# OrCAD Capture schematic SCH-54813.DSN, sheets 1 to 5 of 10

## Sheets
1 01 Title Page, Notes: title: PNEV7642A; rev: B1; company: NXP Semiconductors; note: SCH-54813 PDF: SPF-54813; note: 6501 William Cannon Drive West; note: Austin, TX 78735-8598
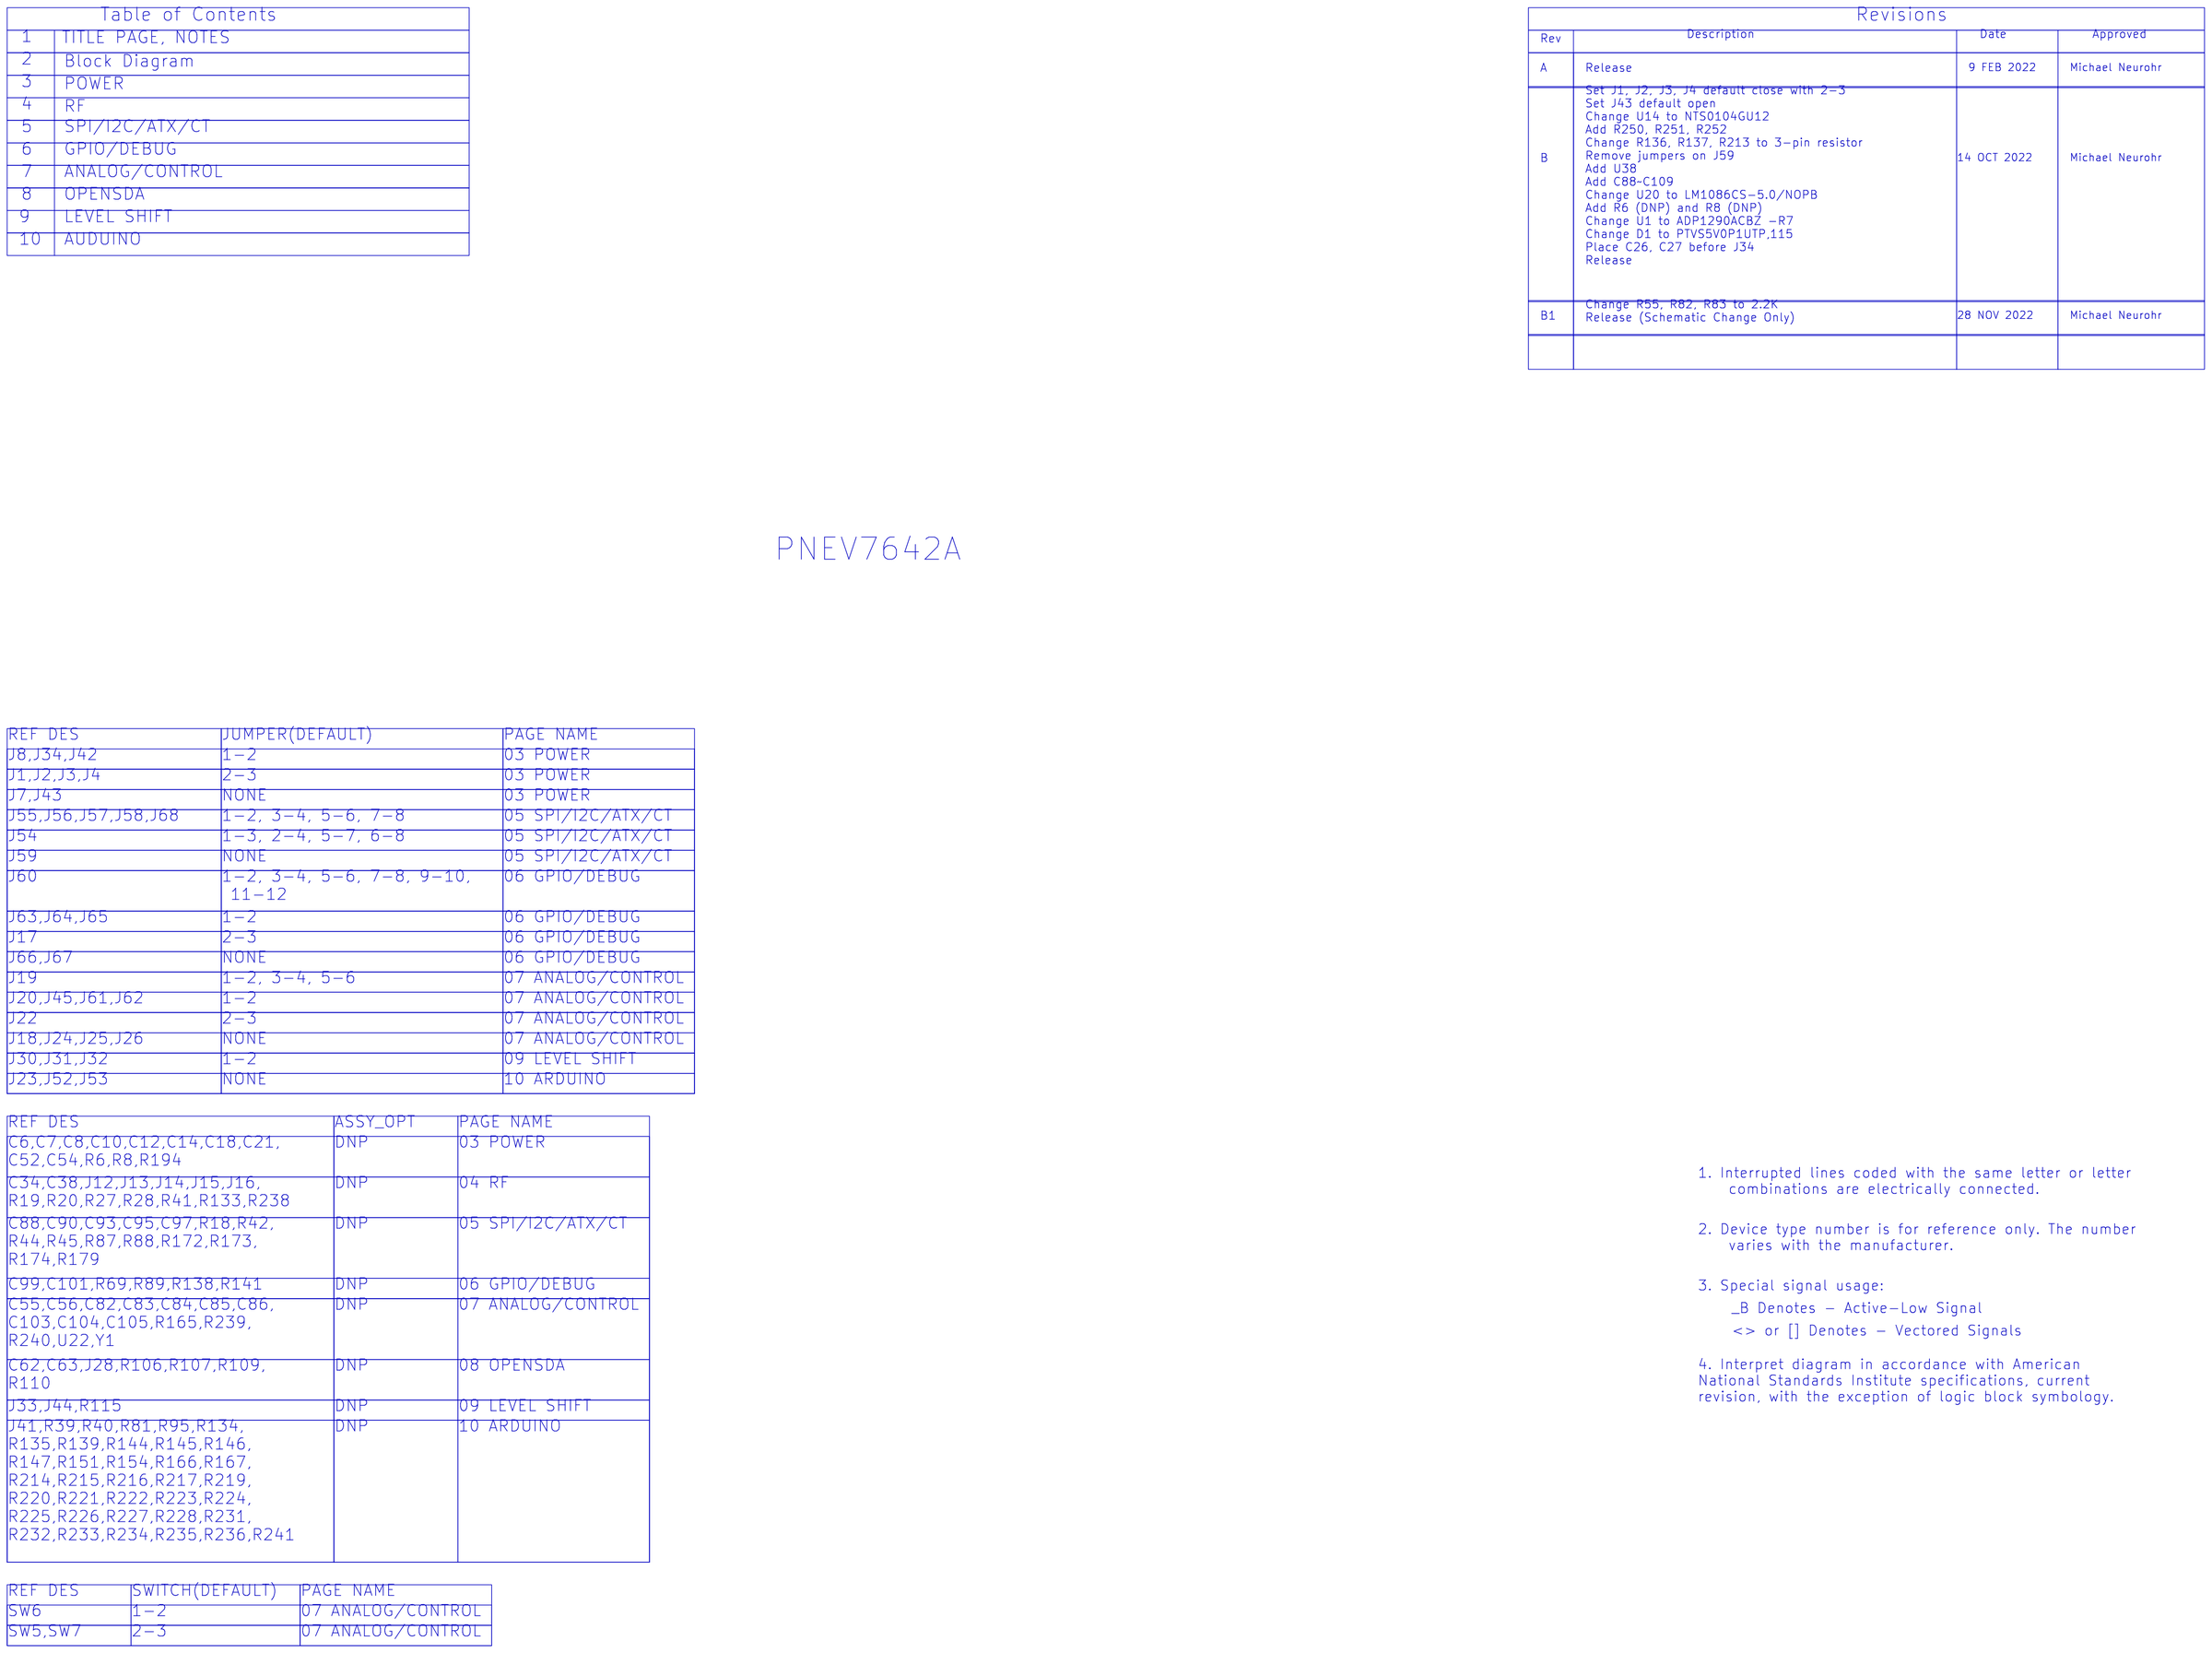
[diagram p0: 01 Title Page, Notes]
2 02 Block Diagram
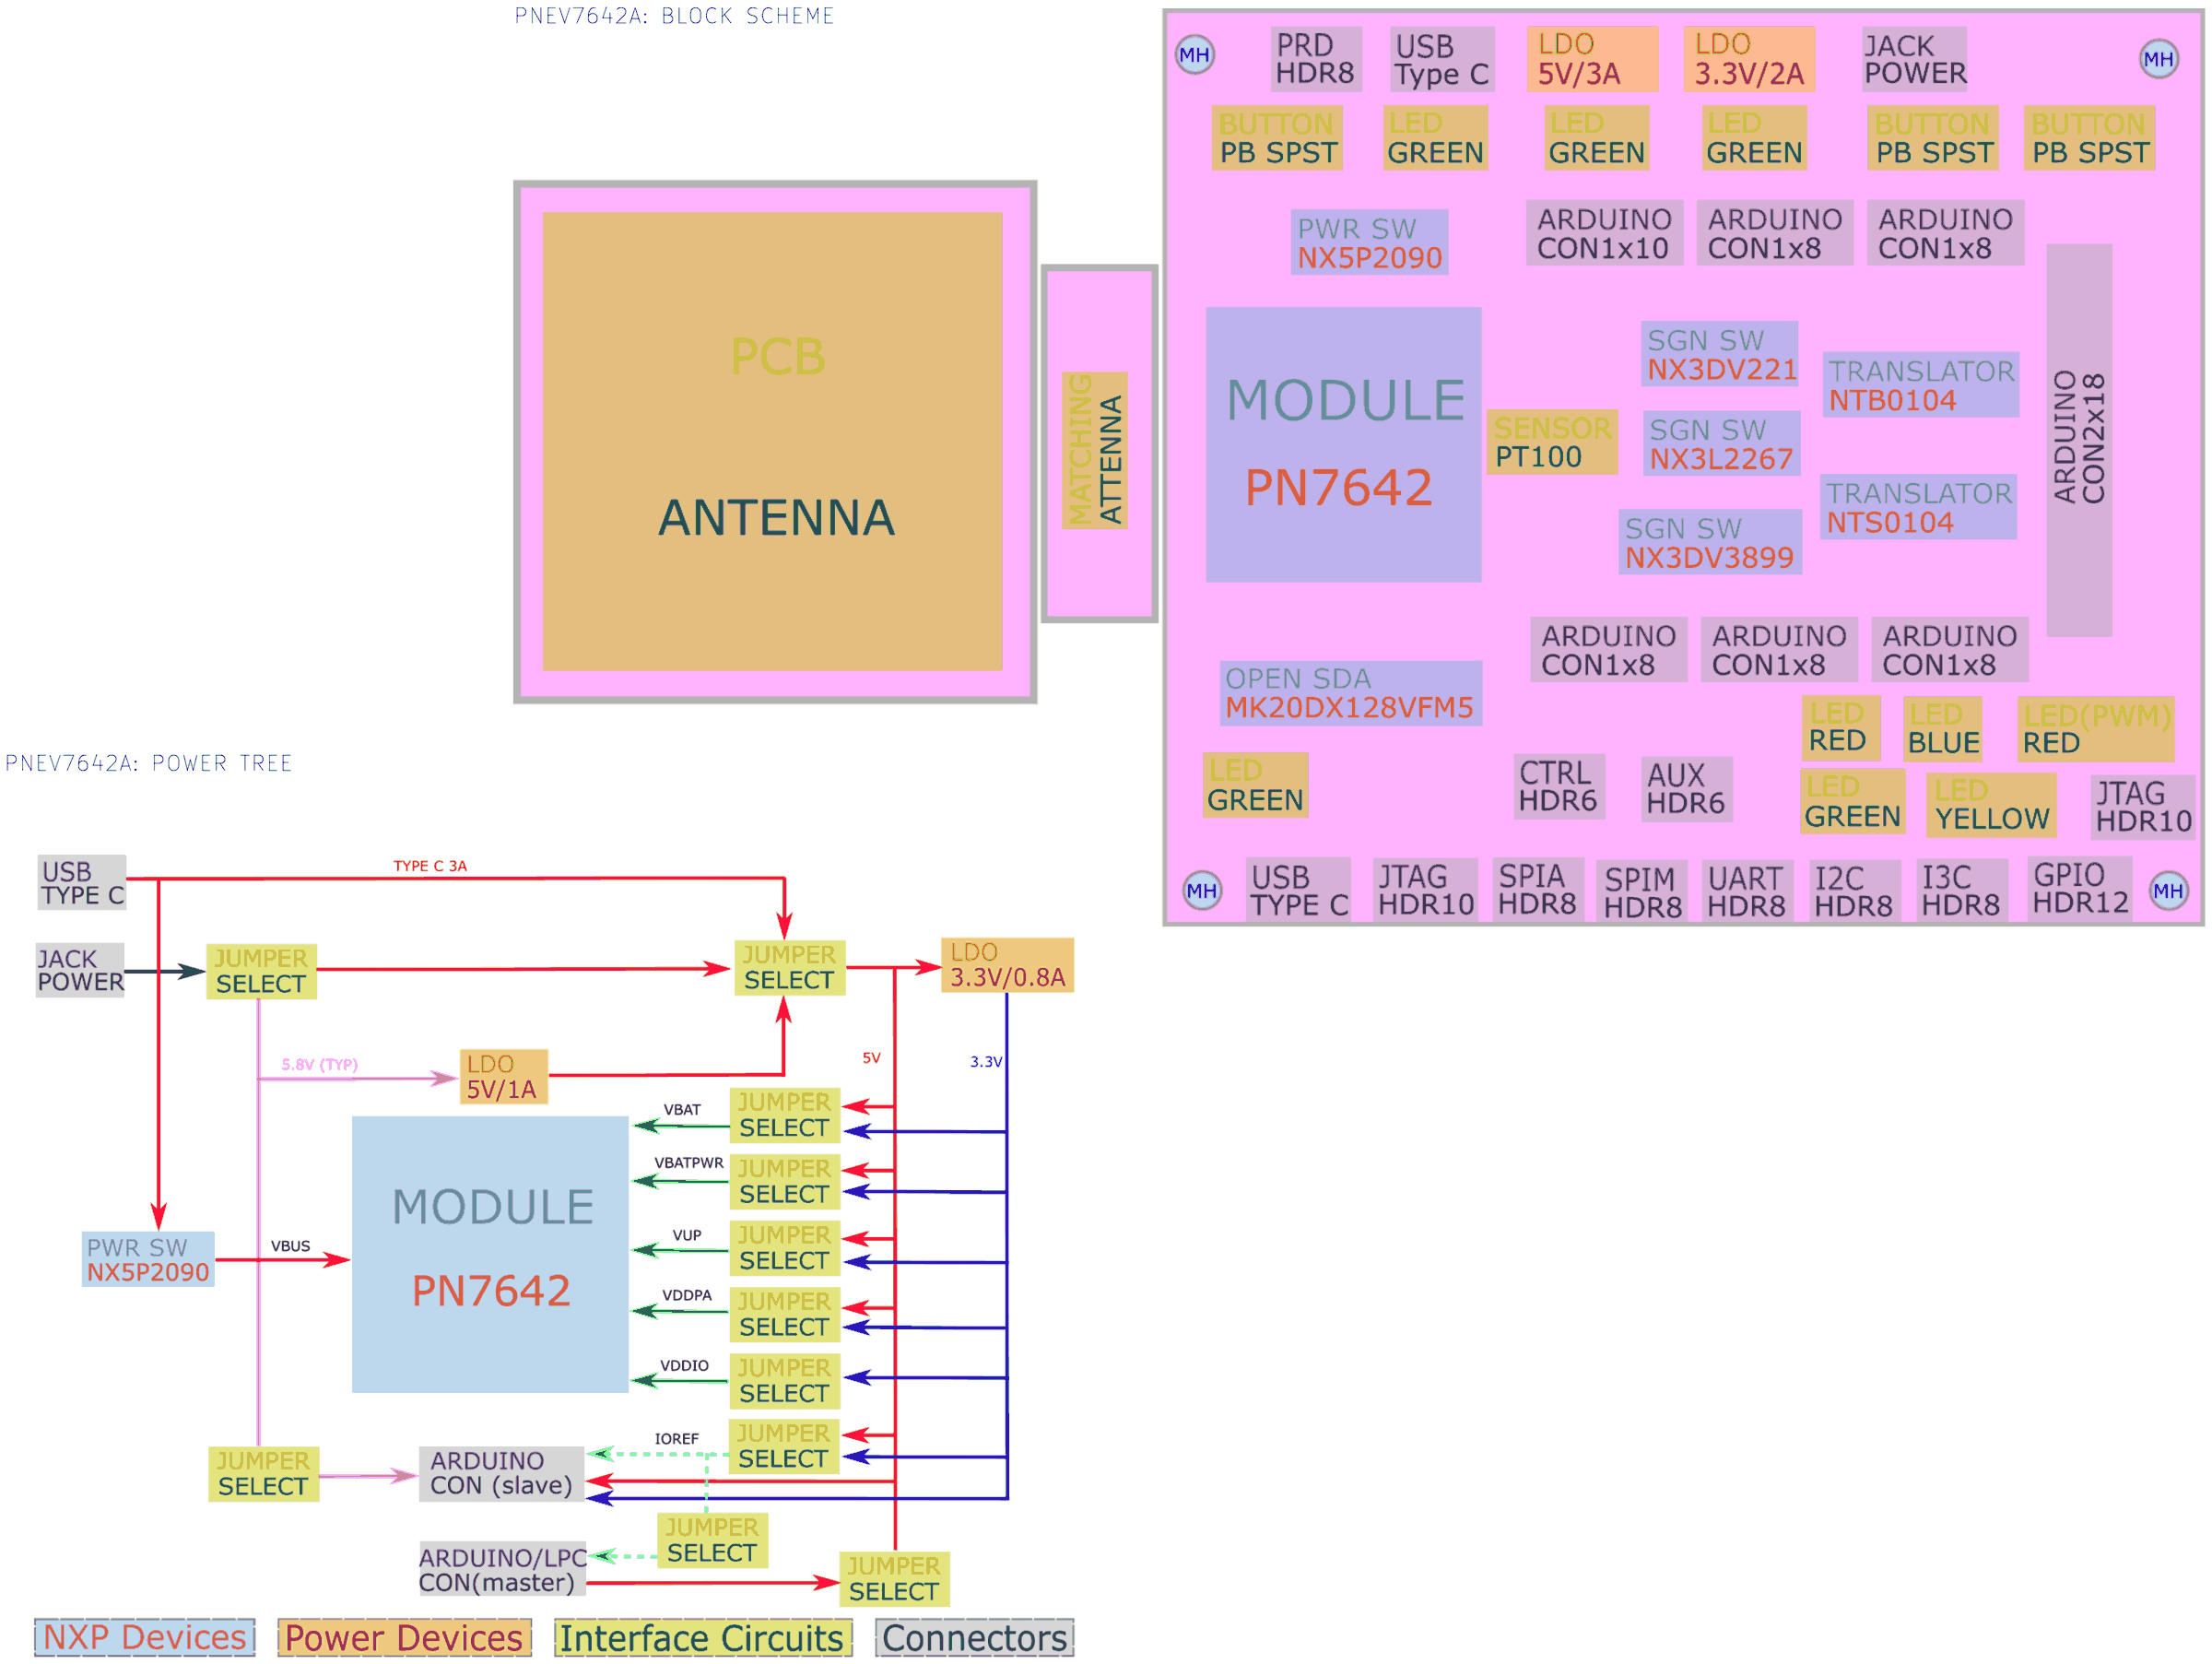
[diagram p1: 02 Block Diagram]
3 03 POWER: size C
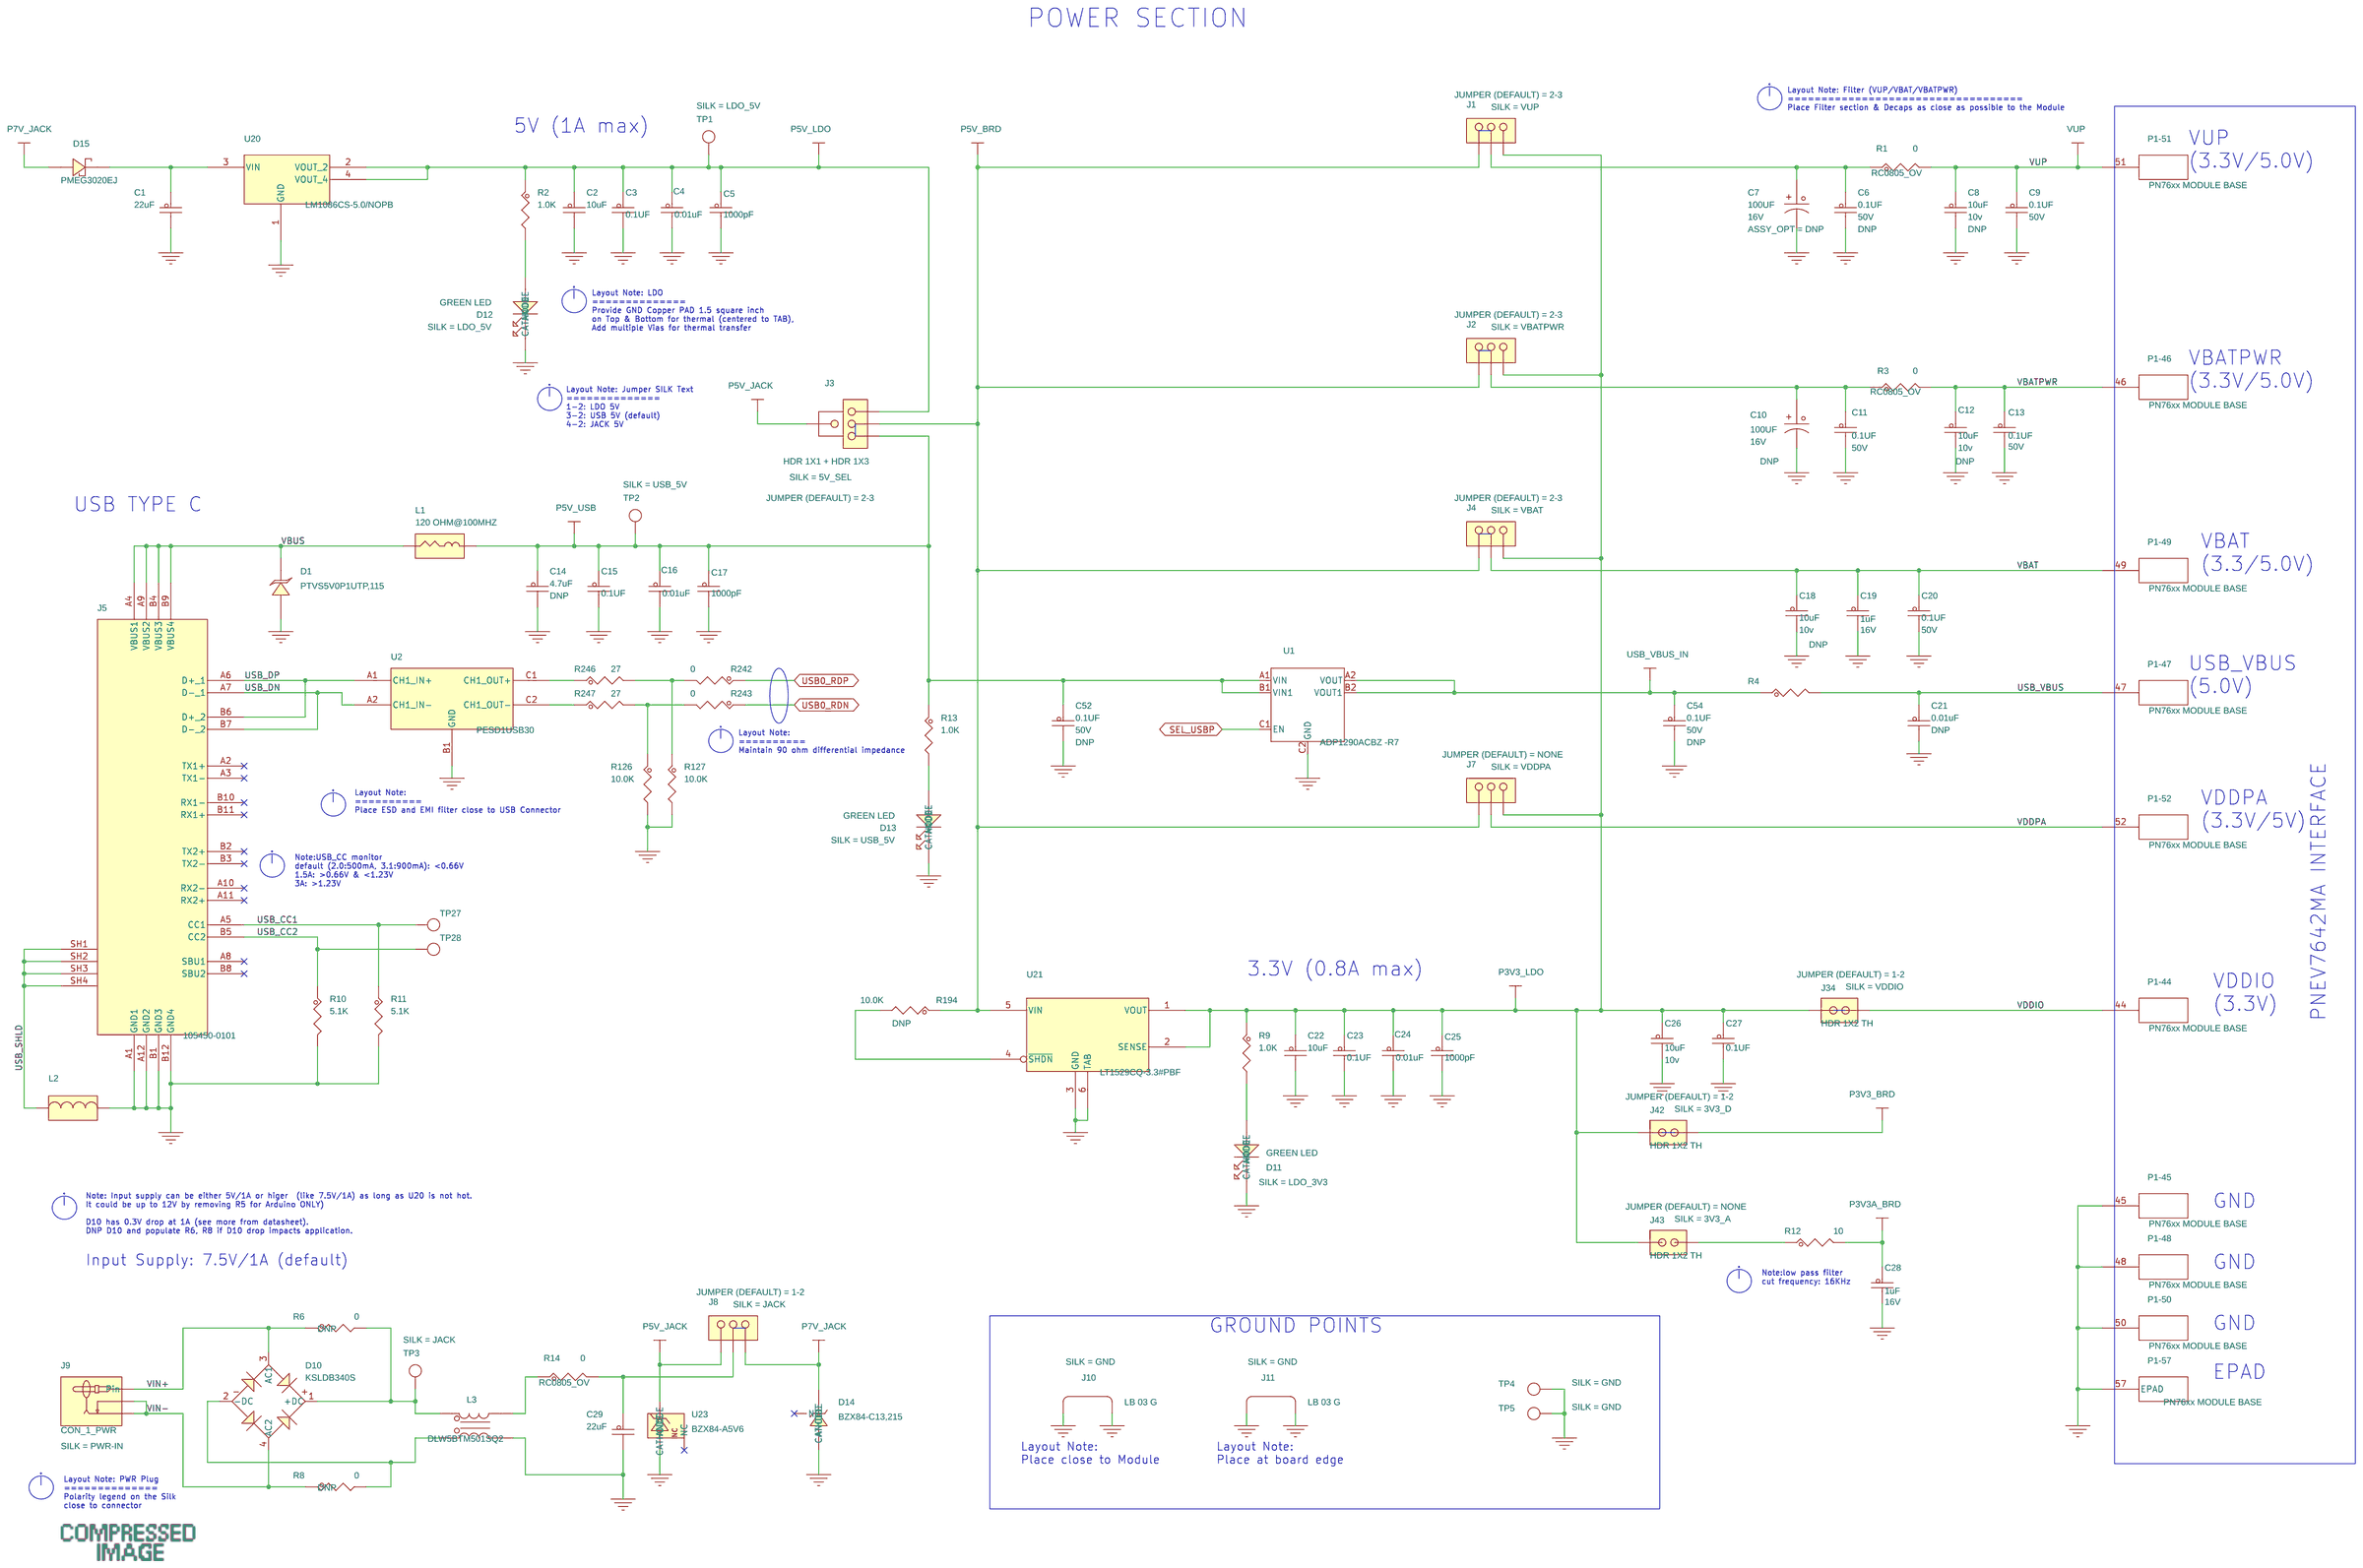
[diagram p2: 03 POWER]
4 04 RF: size C
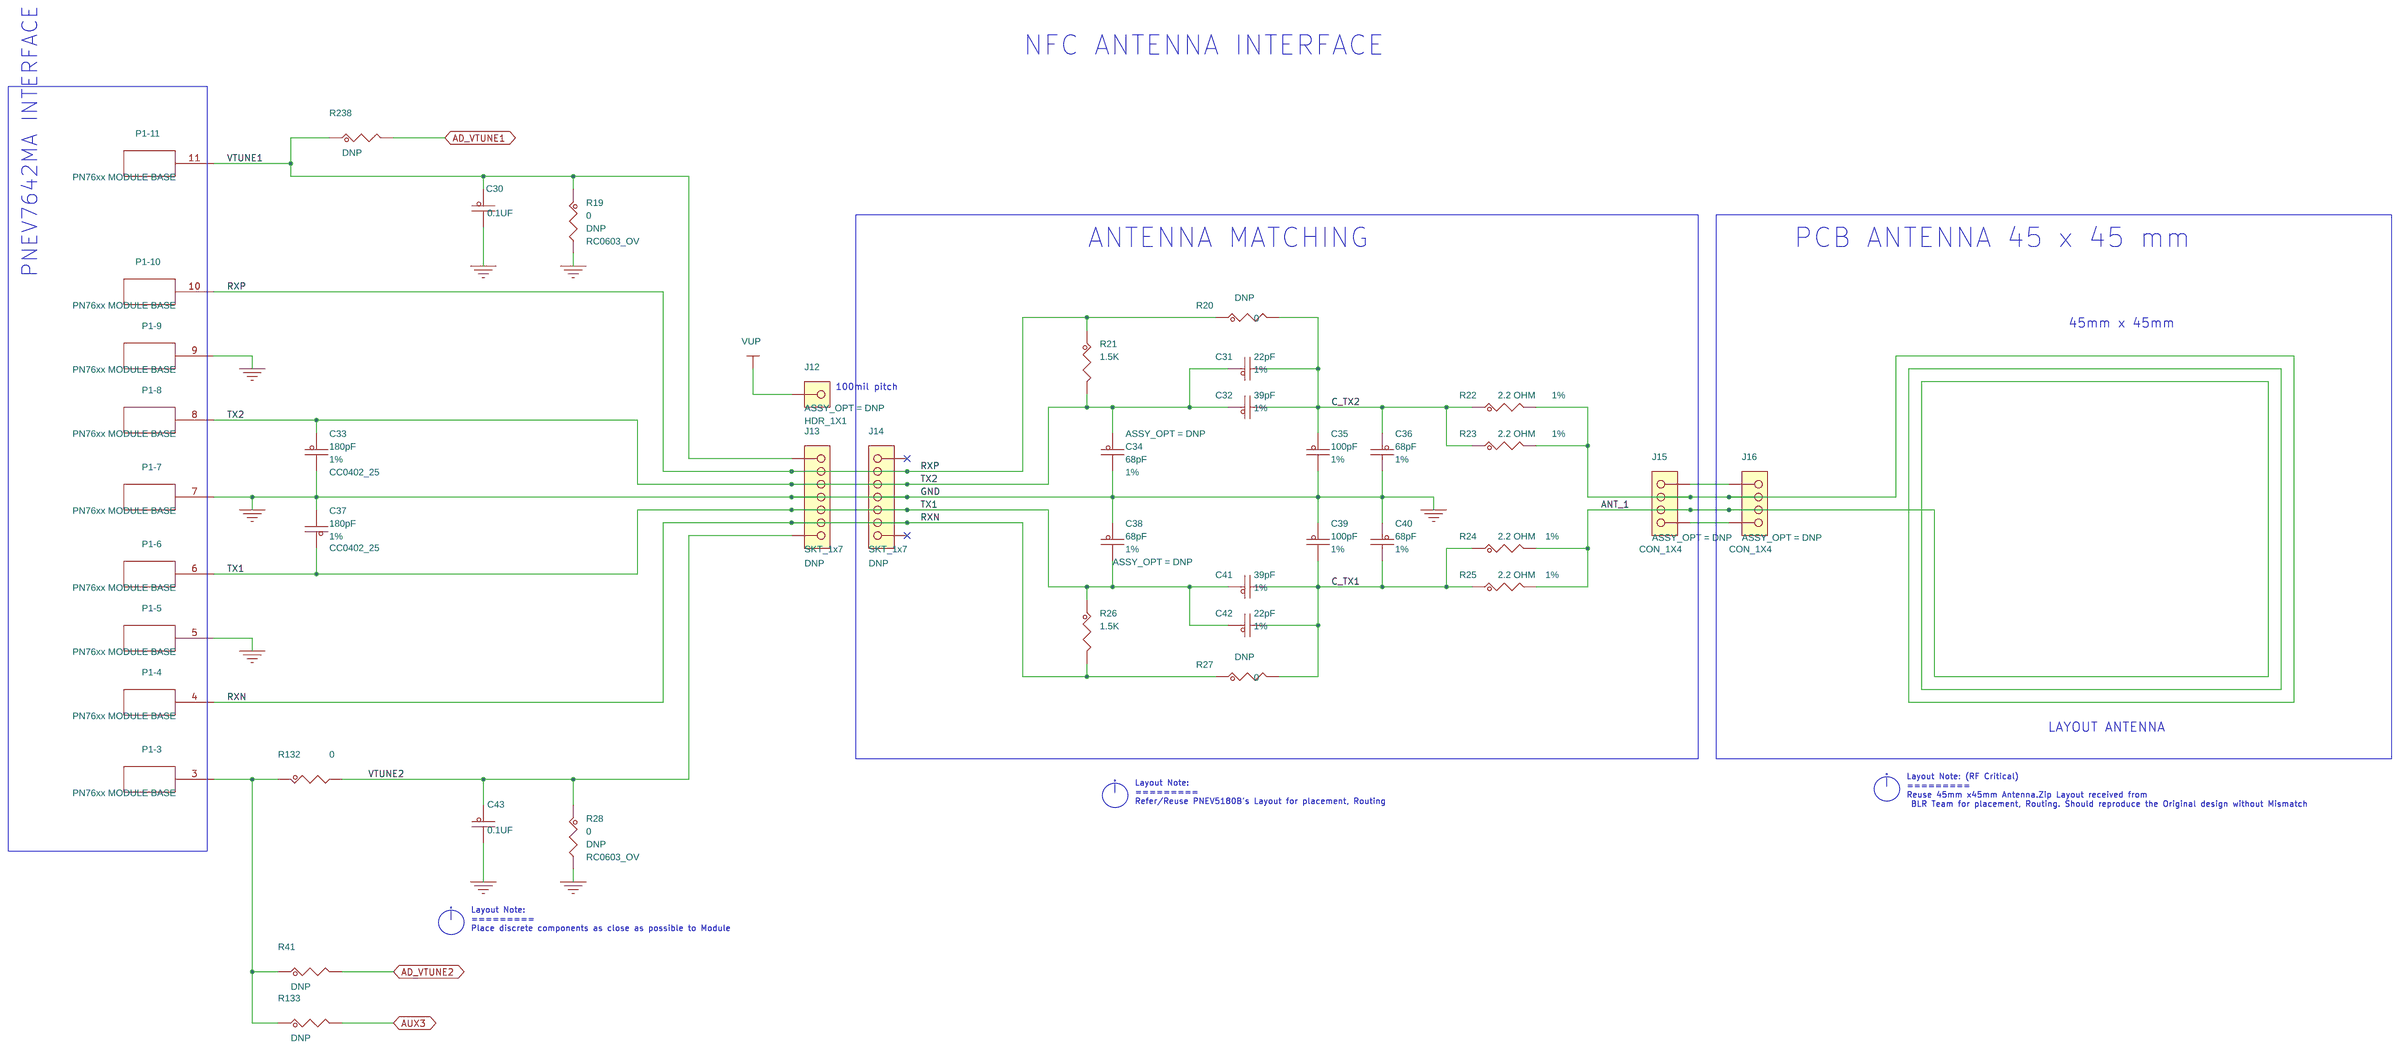
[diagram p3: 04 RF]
5 08 OPENSDA: size C
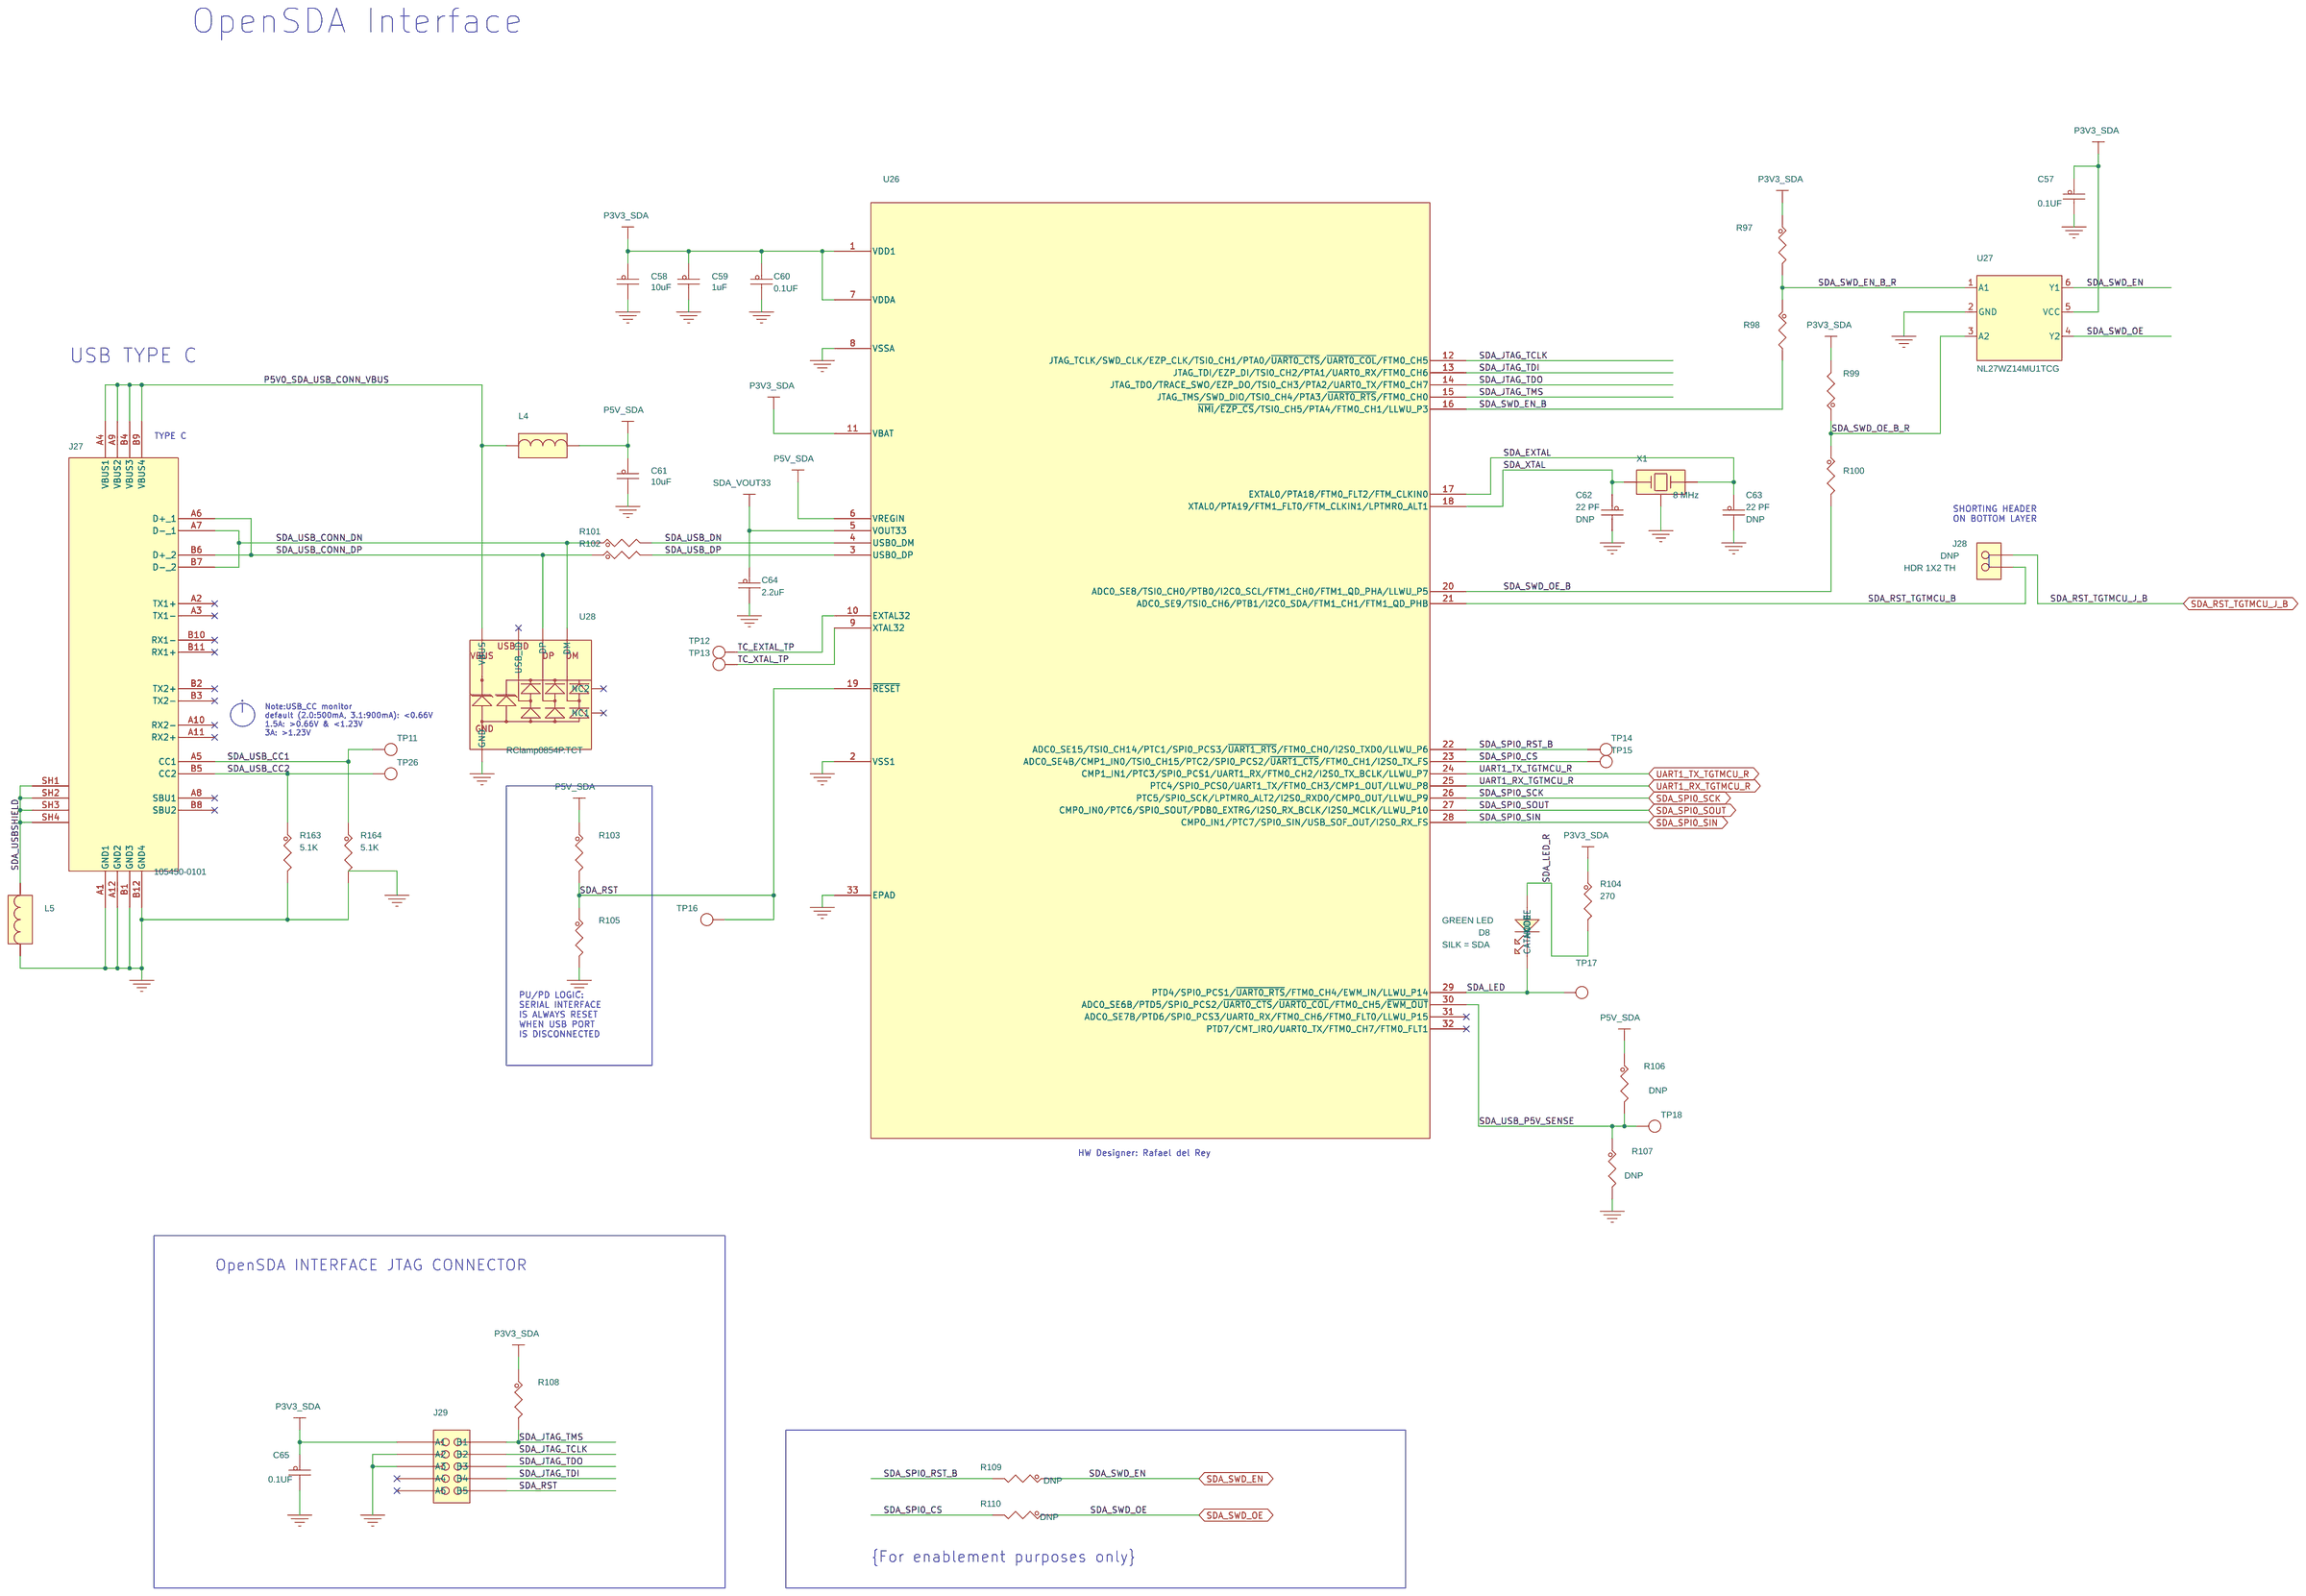
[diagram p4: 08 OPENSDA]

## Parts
sheet 03 POWER
C1  22uF  [CC0805_OV]
C2  10uF  [CC0603_OV]
C3  0.1UF  [CC0402_25]
C4  0.01uF  [CC0402_25]
C5  1000pF  [CC0402_25]
C6  0.1UF  [CC0402_25]
C7  100UF  [CC7343]
C8  10uF  [CC0603_OV]
C9  0.1UF  [CC0402_25]
C10  100UF  [CC7343]
C11  0.1UF  [CC0402_25]
C12  10uF  [CC0603_OV]
C13  0.1UF  [CC0402_25]
C14  4.7uF  [CC0603_OV]
C15  0.1UF  [CC0402_25]
C16  0.01uF  [CC0402_25]
C17  1000pF  [CC0402_25]
C18  10uF  [CC0603_OV]
C19  1uF  [CC0603_OV]
C20  0.1UF  [CC0402_25]
C21  0.01uF  [CC0402_25]
C22  10uF  [CC0603_OV]
C23  0.1UF  [CC0402_25]
C24  0.01uF  [CC0402_25]
C25  1000pF  [CC0402_25]
C26  10uF  [CC0603_OV]
C27  0.1UF  [CC0402_25]
C28  1uF  [CC0603_OV]
C29  22uF  [CC0805_OV]
C52  0.1UF  [CC0402_25]
C54  0.1UF  [CC0402_25]
D1  PTVS5V0P1UTP,115  [sod-128]
D10  KSLDB340S  [diode_sldbs_4p6x5p1]
D11  GREEN LED  [led_0603_h020]
D12  GREEN LED  [led_0603_h020]
D13  GREEN LED  [led_0603_h020]
D14  BZX84-C13,215  [sot23_a]
D15  PMEG3020EJ  [SOD323]
J1  HDR TH 1X3  [HDR103]
J2  HDR TH 1X3  [HDR103]
J3  HDR 1X1 + HDR 1X3  [hdr_4_th_top_bot]
J4  HDR TH 1X3  [HDR103]
J5  105450-0101  [con24_usb_typec_ra_smt]
J7  HDR TH 1X3  [HDR103]
J8  HDR TH 1X3  [HDR103]
J9  CON_1_PWR  [PJ-202B]
J10  LB 03 G  [jump2_7p62_th]
J11  LB 03 G  [jump2_7p62_th]
J34  HDR 1X2 TH  [HDR_1X2]
J42  HDR 1X2 TH  [HDR_1X2]
J43  HDR 1X2 TH  [HDR_1X2]
L1  120 OHM@100MHZ  [IND_0603]
L2  330 OHM  [IND_0805]
L3  DLW5BTM501SQ2  [ind_dlw5bs_2020]
R1  0  [RC0805_OV]
R2  1.0K  [RC0402_25]
R3  0  [RC0805_OV]
R4  1.0K  [RC0402_25]
R6  0  [RC0603_OV]
R8  0  [RC0603_OV]
R9  1.0K  [RC0402_25]
R10  5.1K  [RC0603_OV]
R11  5.1K  [RC0603_OV]
R12  10  [RC0805_OV]
R13  1.0K  [RC0402_25]
R14  0  [RC0805_OV]
R126  10.0K  [RC0402_25]
R127  10.0K  [RC0402_25]
R194  10.0K  [RC0402_25]
R242  0  [RC0603_OV]
R243  0  [RC0603_OV]
R246  27  [RC0402_25]
R247  27  [RC0402_25]
TP1  TEST POINT RED  [TEST_LOOP]
TP2  TEST POINT RED  [TEST_LOOP]
TP3  TEST POINT RED  [TEST_LOOP]
TP4  TEST POINT BLACK  [TEST_LOOP]
TP5  TEST POINT BLACK  [TEST_LOOP]
TP27  TPAD_030  [TPAD_030]
TP28  TPAD_030  [TPAD_030]
U1  ADP1290ACBZ -R7  [wlcsp6_0p5_0p98x1p48]
U2  PESD1USB30  [wlcsp5_0p4_0p82x1p22]
U20  LM1086CS-5.0/NOPB  [to-263-3]
U21  LT1529CQ-3.3#PBF  [DD-PAK5]
U23  BZX84-A5V6  [sot23_a]
sheet 04 RF
C30  0.1UF  [CC0402_25]
C31  22pF  [CC0805_OV]
C32  39pF  [CC0805_OV]
C33  180pF  [CC0402_25]
C34  68pF  [CC0805_OV]
C35  100pF  [CC0805_OV]
C36  68pF  [CC0805_OV]
C37  180pF  [CC0402_25]
C38  68pF  [CC0805_OV]
C39  100pF  [CC0805_OV]
C40  68pF  [CC0805_OV]
C41  39pF  [CC0805_OV]
C42  22pF  [CC0805_OV]
C43  0.1UF  [CC0402_25]
J12  HDR_1X1  [HDR_1X1]
J13  SKT_1x7  [con_1x7_skt_2p54_th]
J14  SKT_1x7  [con_1x7_skt_2p54_th]
J15  CON_1X4  [con_skt1x4_th]
J16  CON_1X4  [con_skt1x4_th]
R19  0  [RC0603_OV]
R20  0  [RC0805_OV]
R21  1.5K  [RC0805_OV]
R22  2.2 OHM  [RC0805_OV]
R23  2.2 OHM  [RC0805_OV]
R24  2.2 OHM  [RC0805_OV]
R25  2.2 OHM  [RC0805_OV]
R26  1.5K  [RC0805_OV]
R27  0  [RC0805_OV]
R28  0  [RC0603_OV]
R41  0  [RC0603_OV]
R132  0  [RC0603_OV]
R133  0  [RC0603_OV]
R238  0  [RC0603_OV]
sheet 06 GPIO/DEBUG
P1  PN76xx MODULE BASE  [module56_1p52_23x23mm]  (sections -1,-10,-11,-12,-13,-14,-15,-16,-17,-18,-19,-2,-20,-21,-22,-23,-24,-25,-26,-27,-28,-29,-3,-30,-31,-32,-33,-34,-35,-36,-37,-38,-39,-4,-40,-41,-42,-43,-44,-45,-46,-47,-48,-49,-5,-50,-51,-52,-53,-54,-55,-56,-57,-6,-7,-8,-9)
sheet 08 OPENSDA
C57  0.1UF  [CC0402_25]
C58  10uF  [CC0603_OV]
C59  1uF  [CC0603_OV]
C60  0.1UF  [CC0402_25]
C61  10uF  [CC0603_OV]
C62  22 PF  [CC0603_OV]
C63  22 PF  [CC0603_OV]
C64  2.2uF  [CC0603_OV]
C65  0.1UF  [CC0402_25]
D8  GREEN LED  [led_0603_h020]
J27  105450-0101  [con24_usb_typec_ra_smt]
J28  HDR 1X2 TH  [SH_HDR102_BOTTOM]
J29  HDR 2X5  [hdr_5X2_ftsh_th_nsp]
L4  330 OHM  [IND_0805]
L5  330 OHM  [IND_0805]
R97  10.0K  [RC0402_25]
R98  0  [RC0603_OV]
R99  10.0K  [RC0402_25]
R100  0  [RC0603_OV]
R101  33  [RC0402_25]
R102  33  [RC0402_25]
R103  4.7K  [RC0402_25]
R104  270  [RC0402_25]
R105  10.0K  [RC0402_25]
R106  4.7K  [RC0402_25]
R107  10.0K  [RC0402_25]
R108  10.0K  [RC0402_25]
R109  0  [RC0603_OV]
R110  0  [RC0603_OV]
R163  5.1K  [RC0603_OV]
R164  5.1K  [RC0603_OV]
TP11  TPAD_030  [TPAD_030]
TP12  TPAD_030  [TPAD_030]
TP13  TPAD_030  [TPAD_030]
TP14  TPAD_030  [TPAD_030]
TP15  TPAD_030  [TPAD_030]
TP16  TPAD_030  [TPAD_030]
TP17  TPAD_030  [TPAD_030]
TP18  TPAD_030  [TPAD_030]
TP26  TPAD_030  [TPAD_030]
U26  MK20DX128VFM5  [QFN32_S142EP]
U27  NL27WZ14MU1TCG  [udfn6_1p45x1_0p5mm]
U28  RClamp0854P.TCT  [slp1616p6]
X1  8 MHz  [XTAL3_3P35X1P45_SM]

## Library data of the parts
C1 C29 = CAP_NP: CAP CER 22uF 25V 20% X5R 0805; AGILE_PN: 150-79304; CAD_APPROVED: Yes; HEIGHT: 1.45MM; MFG_NAME01: MURATA; MFG_PN01: GRM21BR61E226ME44; Package Size: 0805; Package Type: SMD; ROHS: Yes; Rated Voltage: 25V; Temp Range: -55C to +85C; Tolerance: 20%; VOLTAGE: 25V
C2 C22 = CAP_NP: CAP CER 10UF 10V 10% X5R 0603; AGILE_PN: 150-78675; CAD_APPROVED: Yes; FPLIST: CC0603_OV,CC0603,0603_CC_NSP; HEIGHT: 1.016MM; MFG_NAME01: MURATA; MFG_PN01: GRM188R61A106KE69D; ROHS: Yes; Rated Voltage: 10V; Temp Range: -55C to +85C; Tolerance: 10%; VOLTAGE: 10v
C3 C9 C11 C13 C15 C20 C23 C30 C43 = CAP_NP: CAP CER 0.1UF 50V 10% X5R 0402; AGILE_PN: 150-79249; CAD_APPROVED: Yes; FPLIST: CC0402_25,CC0402_HD,0402_CC,capc0402_l; HEIGHT: 0.55MM; MFG_NAME01: MURATA; MFG_PN01: GRM155R61H104KE19; ROHS: Yes; Rated Voltage: 50V; Temp Range: -55C to +85C; Tolerance: 10%; VOLTAGE: 50V
C4 C16 C24 = CAP_NP: CAP CER 0.01UF 25V 10% X7R 0402; AGILE_PN: 150-75183; CAD_APPROVED: Yes; FPLIST: CC0402_25,CC0402_HD,0402_CC; HEIGHT: 0.635mm; MFG_NAME01: AVX; MFG_PN01: 04023C103KAT2A; ROHS: Yes; Rated Voltage: 25V; Temp Range: -55C to +125C; Tolerance: 10%; VOLTAGE: 25V
C5 C17 C25 = CAP_NP: CAP CER 1000pF 50V 10% X7R AEC-Q200 0402; AGILE_PN: 150-79040; CAD_APPROVED: Yes; FPLIST: CC0402_25,CC0402_HD,0402_CC; HEIGHT: 0.55MM; MFG_NAME01: MURATA; MFG_PN01: GCM155R71H102KA37D; Package Size: 0402; Package Type: Paper Tape; ROHS: Yes; Rated Voltage: 50V; Temp Range: -55C to +125C; Tolerance: 10%; VOLTAGE: 50V
C6 C52 C54 = CAP_NP: CAP CER 0.1UF 50V 10% X5R 0402; AGILE_PN: 150-79249; ASSY_OPT: DNP; CAD_APPROVED: Yes; FPLIST: CC0402_25,CC0402_HD,0402_CC,capc0402_l; HEIGHT: 0.55MM; MFG_NAME01: MURATA; MFG_PN01: GRM155R61H104KE19; ROHS: Yes; Rated Voltage: 50V; Temp Range: -55C to +85C; Tolerance: 10%; VOLTAGE: 50V
C7 C10 = CAP_POL: CAP TANT ESR=0.1 OHM 100UF 16V 10% -- 7343-43; 3D_Mechanical_Footprint_File: http://fcl.am.freescale.net/ALLEGRO/step/cc7343.step; AGILE_PN: 150-75159; ASSY_OPT: DNP; CAD_APPROVED: YES; HEIGHT: 4.3MM; MFG_NAME01: AVX; MFG_PN01: TPSE107K016R0100; Package Size: 7343-43; Package Type: 7; ROHS: Yes; Rated Voltage: 16V; Tolerance: 10%; VOLTAGE: 16V
C8 C12 = CAP_NP: CAP CER 10UF 10V 10% X5R 0603; AGILE_PN: 150-78675; ASSY_OPT: DNP; CAD_APPROVED: Yes; FPLIST: CC0603_OV,CC0603,0603_CC_NSP; HEIGHT: 1.016MM; MFG_NAME01: MURATA; MFG_PN01: GRM188R61A106KE69D; ROHS: Yes; Rated Voltage: 10V; Temp Range: -55C to +85C; Temp_Range: -55°C to +85°C; Tolerance: 10%; VOLTAGE: 10v
C14 = CAP_NP: CAP CER 4.7uF 16V 10% X5R 0603; AGILE_PN: 150-80061; ASSY_OPT: DNP; CAD_APPROVED: Yes; HEIGHT: 0.95MM; MFG_NAME01: MURATA; MFG_PN01: GRM188R61C475KE11D; ROHS: Yes; Rated Voltage: 16V; Temp Range: -55C to +85C; Tolerance: 10%; VOLTAGE: 16V
C18 = CAP_NP: CAP CER 10UF 10V 10% X5R 0603; AGILE_PN: 150-78675; ASSY_OPT: DNP; CAD_APPROVED: Yes; FPLIST: CC0603_OV,CC0603,0603_CC_NSP; HEIGHT: 1.016MM; MFG_NAME01: MURATA; MFG_PN01: GRM188R61A106KE69D; ROHS: Yes; Rated Voltage: 10V; TOL: 10%; Temp Range: -55C to +85C; Temp_Range: -55°C to +85°C; Tolerance: 10%; VOLTAGE: 10v
C19 C28 C59 = CAP_NP: CAP CER 1uF 16V 10% X7R 0603; AGILE_PN: 150-79460; CAD_APPROVED: Yes; FPLIST: CC0603_OV,CC0603,0603_CC; HEIGHT: 0.9 MM; MFG_NAME01: TDK; MFG_PN01: C1608X7R1C105K080AC; Package Size: 0603; ROHS: Yes; Rated Voltage: 16V; Temp Range: -55C to +125C; Tolerance: 10%; VOLTAGE: 16V
C21 = CAP_NP: CAP CER 0.01UF 25V 10% X7R 0402; AGILE_PN: 150-75183; ASSY_OPT: DNP; CAD_APPROVED: Yes; FPLIST: CC0402_25,CC0402_HD,0402_CC; HEIGHT: 0.635mm; MFG_NAME01: AVX; MFG_PN01: 04023C103KAT2A; ROHS: Yes; Rated Voltage: 25V; Temp Range: -55C to +125C; Tolerance: 10%; VOLTAGE: 25V
C26 = CAP_NP: CAP CER 10UF 10V 10% X5R 0603; AGILE_PN: 150-78675; CAD_APPROVED: Yes; FPLIST: CC0603_OV,CC0603,0603_CC_NSP; HEIGHT: 1.016MM; MFG_NAME01: MURATA; MFG_PN01: GRM188R61A106KE69D; ROHS: Yes; Rated Voltage: 10V; TOL: 10%; Temp Range: -55C to +85C; Temp_Range: -55°C to +85°C; Tolerance: 10%; VOLTAGE: 10v
C27 C57 C60 C65 = CAP_NP: CAP CER 0.1UF 50V 10% X5R 0402; AGILE_PN: 150-79249; CAD_APPROVED: Yes; FPLIST: CC0402_25,CC0402_HD,0402_CC,capc0402_l; HEIGHT: 0.55MM; MFG_NAME01: MURATA; MFG_PN01: GRM155R61H104KE19; ROHS: Yes; Rated Voltage: 50V; TOL: 10%; Temp Range: -55C to +85C; Tolerance: 10%; VOLTAGE: 50V
D1 = DIODE_TVS: DIODE TVS ESD 600W VRWM 5V AEC-Q101 SOD128; 3D_Mechanical_Footprint_File: http://fcl.am.freescale.net/ALLEGRO/step/sod-128.STEP; AGILE_PN: 480-80340; CAD_APPROVED: yes; HEIGHT: 1.1 MM; MFG_NAME01: Nexperia; Package Size: SOD-128-2; Rated Power: 600W; Rated Voltage: 5.0V; Temp Range: -55°C to +185°C
D10 = DF04S: DIODE RECT BRIDGE SCH 3A 40V SMT; AGILE_PN: 480-80429; CAD_APPROVED: YES; HEIGHT: 1.5 MM; MFG_NAME01: Rectron USA; Package Size: 4-SMD, Gull Wing; Rated Voltage: 40V; Temp Range: -55°C ~ 150°C; VOLTAGE: 40V
D11 = LED: LED GRN SGL 20MA 2V SMT 0603; 3D_Mechanical_Footprint_File: http://fcl.am.freescale.net/ALLEGRO/step/led_0603_h020.STEP; AGILE_PN: 370-76819; CAD_APPROVED: YES; HEIGHT: 0.5 mm; MFG_NAME01: WURTH ELEKTRONIK EISOS GMBH & CO. KG (ELECTRONIC & ELECTROMEHANICAL COMP); MFG_PN01: 150060VS55040; Package Size: 0603 (1608 metric); SILK: LDO_3V3
D12 = LED: LED GRN SGL 20MA 2V SMT 0603; 3D_Mechanical_Footprint_File: http://fcl.am.freescale.net/ALLEGRO/step/led_0603_h020.STEP; AGILE_PN: 370-76819; CAD_APPROVED: YES; HEIGHT: 0.5 mm; MFG_NAME01: WURTH ELEKTRONIK EISOS GMBH & CO. KG (ELECTRONIC & ELECTROMEHANICAL COMP); MFG_PN01: 150060VS55040; Package Size: 0603 (1608 metric); SILK: LDO_5V
D13 = LED: LED GRN SGL 20MA 2V SMT 0603; 3D_Mechanical_Footprint_File: http://fcl.am.freescale.net/ALLEGRO/step/led_0603_h020.STEP; AGILE_PN: 370-76819; CAD_APPROVED: YES; HEIGHT: 0.5 mm; MFG_NAME01: WURTH ELEKTRONIK EISOS GMBH & CO. KG (ELECTRONIC & ELECTROMEHANICAL COMP); MFG_PN01: 150060VS55040; Package Size: 0603 (1608 metric); SILK: USB_5V
D14 = BZX84C27: DIODE ZNR 250mW 13V AEC-Q101 SOT23; AGILE_PN: 480-80414; CAD_APPROVED: YES; HEIGHT: 1.1 MM; MFG_NAME01: Nexperia; Package Size: SOT-23-3; Rated Voltage: 13V; Temp Range: -65 +150°C; VOLTAGE: 13V
D15 = DIODE_SCHTKY: DIODE SCH PWR RECT 2A 30V  SOD323F; AGILE_PN: 480-79723; CAD_APPROVED: Yes; HEIGHT: 0.8MM; MFG_NAME01: NEXPERIA; MFG_PN01: PMEG3020EJ,115
J1 = CONN_HDR_3X1: HDR 1X3 TH 100MIL SP 339H AU 100L; 3D_Mechanical_Footprint_File: http://fcl.am.freescale.net/ALLEGRO/step/hdr103.STEP; AGILE_PN: 210-75726; CAD_APPROVED: Yes; HEIGHT: 8.65MM; JUMPER (DEFAULT): 2-3; MFG_NAME01: SAMTEC; MFG_PN01: TSW-103-07-G-S; Package Size: 7.62 x 2.54 mm; ROHS: Yes; SILK: VUP; Temp Range: -55°C to +125°C; VOLTAGE: 450 - 550 VAC
J2 = CONN_HDR_3X1: HDR 1X3 TH 100MIL SP 339H AU 100L; 3D_Mechanical_Footprint_File: http://fcl.am.freescale.net/ALLEGRO/step/hdr103.STEP; AGILE_PN: 210-75726; CAD_APPROVED: Yes; HEIGHT: 8.65MM; JUMPER (DEFAULT): 2-3; MFG_NAME01: SAMTEC; MFG_PN01: TSW-103-07-G-S; Package Size: 7.62 x 2.54 mm; ROHS: Yes; SILK: VBATPWR; Temp Range: -55°C to +125°C; VOLTAGE: 450 - 550 VAC
J3 = HDR_1X1_1X3: SUBASSEMBLY HDR 1X1 TH -- 330H AU 100L + HDR 1X3 TH 100MIL SP 370H AU 118L; 3D_Mechanical_Footprint_File: http://fcl.am.freescale.net/ALLEGRO/step/hdr_4_th_top_bot.STEP; AGILE_PN: 750-78228; CAD_APPROVED: Yes; HEIGHT: 9.4MM; JUMPER (DEFAULT): 2-3; MFG_NAME01: SUBASSEBMLY; MFG_PN01: 210-82119 (HDR TH 1X3), 210-75767 (HDR 1X1); ROHS: Yes; SILK: 5V_SEL
J4 = CONN_HDR_3X1: HDR 1X3 TH 100MIL SP 339H AU 100L; 3D_Mechanical_Footprint_File: http://fcl.am.freescale.net/ALLEGRO/step/hdr103.STEP; AGILE_PN: 210-75726; CAD_APPROVED: Yes; HEIGHT: 8.65MM; JUMPER (DEFAULT): 2-3; MFG_NAME01: SAMTEC; MFG_PN01: TSW-103-07-G-S; Package Size: 7.62 x 2.54 mm; ROHS: Yes; SILK: VBAT; Temp Range: -55°C to +125°C; VOLTAGE: 450 - 550 VAC
J5 J27 = USB24_TYPEC_105450: CON 24 USB TYPE C  0.5MM RA SHLD SKT SP 134H AU; 3D_Mechanical_Footprint_File: http://fcl.am.freescale.net/ALLEGRO/step/con24_usb_typec_ra_smt.step; AGILE_PN: 211-80150; CAD_APPROVED: Yes; HEIGHT: 3.41MM; MFG_NAME01: MOLEX; ROHS: Yes
J7 = CONN_HDR_3X1: HDR 1X3 TH 100MIL SP 339H AU 100L; 3D_Mechanical_Footprint_File: http://fcl.am.freescale.net/ALLEGRO/step/hdr103.STEP; AGILE_PN: 210-75726; CAD_APPROVED: Yes; HEIGHT: 8.65MM; JUMPER (DEFAULT): NONE; MFG_NAME01: SAMTEC; MFG_PN01: TSW-103-07-G-S; Package Size: 7.62 x 2.54 mm; ROHS: Yes; SILK: VDDPA; Temp Range: -55°C to +125°C; VOLTAGE: 450 - 550 VAC
J8 = CONN_HDR_3X1: HDR 1X3 TH 100MIL SP 339H AU 100L; 3D_Mechanical_Footprint_File: http://fcl.am.freescale.net/ALLEGRO/step/hdr103.STEP; AGILE_PN: 210-75726; CAD_APPROVED: Yes; HEIGHT: 8.65MM; JUMPER (DEFAULT): 1-2; MFG_NAME01: SAMTEC; MFG_PN01: TSW-103-07-G-S; Package Size: 7.62 x 2.54 mm; ROHS: Yes; SILK: JACK; Temp Range: -55°C to +125°C; VOLTAGE: 450 - 550 VAC
J9 = DC_POWER_JACK: CON 1 PWR PLUG DIAM 2.0MM RA TH -- 430H NI; AGILE_PN: 210-30177; CAD_APPROVED: Yes; FPLIST: PJ-202B,pj-202b_nsp; HEIGHT: 11MM; MFG_NAME01: CUI STACK; MFG_PN01: PJ-202A; Package Size: 14.5 x 11MM; ROHS: Yes; SILK: PWR-IN; Temp Range: -25°C to +85°C
J10 J11 = JUMPER1X2_TH: CON 1X2 JUMPER TH 7.62MM 79H AU 276L; 3D_Mechanical_Footprint_File: http://fcl.am.freescale.net/ALLEGRO/step/jump2_7p62_th.STEP; AGILE_PN: 210-81045; CAD_APPROVED: Yes; HEIGHT: 2MM; MFG_NAME01: FISCHER ELECTRONIC; ROHS: Yes; SILK: GND
J34 = HDR_1X2_TH: HDR 1X2 TH 100MIL SP 339H AU 98L; 3D_Mechanical_Footprint_File: http://fcl.am.freescale.net/ALLEGRO/step/hdr102_338h.STEP; AGILE_PN: 210-75439; CAD_APPROVED: YES; FPLIST: HDR102,SH_HDR102_BOTTOM; HEIGHT: 8.71 MM; JUMPER (DEFAULT): 1-2; MFG_NAME01: SAMTEC; MFG_PN01: TSW-102-07-G-S; ROHS: Yes; SILK: VDDIO; Temp Range: -55°C to +125°C
J42 = HDR_1X2_TH: HDR 1X2 TH 100MIL SP 339H AU 98L; 3D_Mechanical_Footprint_File: http://fcl.am.freescale.net/ALLEGRO/step/hdr102_338h.STEP; AGILE_PN: 210-75439; CAD_APPROVED: YES; FPLIST: HDR102,SH_HDR102_BOTTOM; HEIGHT: 8.71 MM; JUMPER (DEFAULT): 1-2; MFG_NAME01: SAMTEC; MFG_PN01: TSW-102-07-G-S; ROHS: Yes; SILK: 3V3_D; Temp Range: -55°C to +125°C
J43 = HDR_1X2_TH: HDR 1X2 TH 100MIL SP 339H AU 98L; 3D_Mechanical_Footprint_File: http://fcl.am.freescale.net/ALLEGRO/step/hdr102_338h.STEP; AGILE_PN: 210-75439; CAD_APPROVED: YES; FPLIST: HDR102,SH_HDR102_BOTTOM; HEIGHT: 8.71 MM; JUMPER (DEFAULT): NONE; MFG_NAME01: SAMTEC; MFG_PN01: TSW-102-07-G-S; ROHS: Yes; SILK: 3V3_A; Temp Range: -55°C to +125°C
L1 = BLM18R: IND FER BEAD 120 OHM@100MHZ 3A 25% 0603; AGILE_PN: 180-77625; CAD_APPROVED: Yes; HEIGHT: 0.65MM; MFG_NAME01: MURATA; MFG_PN01: BLM18SG121TN1D; Package Size: 0603; ROHS: Yes
L2 = BEAD: IND FER BEAD 330OHM@100MHZ 2.5A -- SMT; 3D_Mechanical_Footprint_File: http://fcl.am.freescale.net/ALLEGRO/step/ind_0805.STEP; AGILE_PN: 180-30021; CAD_APPROVED: YES; HEIGHT: 1.05 MM; MFG_NAME01: TDK; MFG_PN01: MPZ2012S331AT000; PART_TYPE: FERRITE; ROHS: Yes; TOL: 25%; Temp Range: -55°C to +125°C; Tolerance: 25%
L3 = DLW43: IND CHK 500OHM@100MHZ 4A -- 2020; 3D_Mechanical_Footprint_File: http://fcl.am.freescale.net/ALLEGRO/step/ind_dlw5bs_2020_98h.STEP; AGILE_PN: 180-78138; CAD_APPROVED: Yes; HEIGHT: 2.5MM; MFG_NAME01: MURATA; ROHS: Yes; VOLTAGE: 50V
R1 R3 R14 = RES: RES MF ZERO OHM 1/8W -- 0805; AGILE_PN: 470-75442; CAD_APPROVED: Yes; FPLIST: RC0805_OV,RC0805,RC0805_OV_3P,0805_CC; HEIGHT: 0.7 MM; MFG_NAME01: YAGEO AMERICA; MFG_PN01: RC0805JR-070RL; ROHS: Yes; Temp Range: –55 °C to +155 °C; Tolerance: 5%
R2 R9 R13 = RES: RES MF 1.0K 1/16W 1% 0402; AGILE_PN: 470-76037; CAD_APPROVED: Yes; FPLIST: RC0402_25,RC0402_HD,RC0402_X2,0402_CC; HEIGHT: 0.4MM; MFG_NAME01: VISHAY; MFG_PN01: CRCW04021K00FKEDC; ROHS: Yes; Tolerance: 1%; VOLTAGE: 1/16W
R4 = RES: RES MF 1.0K 1/16W 1% 0402; AGILE_PN: 470-76037; CAD_APPROVED: Yes; FPLIST: RC0402_25,RC0402_HD,RC0402_X2,0402_CC; HEIGHT: 0.4MM; MFG_NAME01: VISHAY; MFG_PN01: CRCW04021K00FKEDC; ROHS: Yes; TOL: 1%; Tolerance: 1%; VOLTAGE: 1/16W
R6 R8 R19 R28 R109 R110 = RES: RES MF ZERO OHM 1/10W -- 0603; AGILE_PN: 470-80866; ASSY_OPT: DNP; CAD_APPROVED: Yes; FPLIST: RC0603_OV,RC0603,R603-X2,0603_CC,IND_0603HP_NSP,CC0603_OV_NSP; HEIGHT: 0.6MM; MFG_NAME01: YAGEO AMERICA; MFG_PN01: RC0603FR-070RL; ROHS: Yes; Temp Range: –55 °C to +155 °C
R10 R11 R163 R164 = RES: RES MF 5.1K 1/10W 1% 0603; AGILE_PN: 470-80925; CAD_APPROVED: Yes; HEIGHT: 0.55 MM; MFG_NAME01: YAGEO AMERICA; MFG_PN01: RC0603FR-075K1L; ROHS: Yes; Tolerance: 1%
R12 = RES: RES MF 10.0 OHM 1/8W 1% 0805; AGILE_PN: 470-75903; CAD_APPROVED: Yes; HEIGHT: 0.70 MM; MFG_NAME01: BOURNS; MFG_PN01: CR0805-FX-10R0ELF; ROHS: Yes; Tolerance: 1%
R126 R127 = RES: RES MF 10.0K 1/16W 1% AEC-Q200 0402; AGILE_PN: 470-75416; CAD_APPROVED: Yes; FPLIST: RC0402_25,RC0402_HD,0402_CC; HEIGHT: 0.4MM; MFG_NAME01: KOA SPEER; MFG_PN01: RK73H1ETTP1002F; ROHS: Yes; SIGNAL_MODEL: DEFAULT_RESISTOR_10000OHM_2_1; TOL: 5%; Temp Range: –55 °C to +155 °C; Tolerance: 1%
R194 = RES: RES MF 10.0K 1/16W 1% AEC-Q200 0402; AGILE_PN: 470-75416; ASSY_OPT: DNP; CAD_APPROVED: Yes; FPLIST: RC0402_25,RC0402_HD,0402_CC; HEIGHT: 0.4MM; MFG_NAME01: KOA SPEER; MFG_PN01: RK73H1ETTP1002F; ROHS: Yes; SIGNAL_MODEL: DEFAULT_RESISTOR_10000OHM_2_1; TOL: 5%; Temp Range: –55 °C to +155 °C; Tolerance: 1%
R132 R242 R243 = RES: RES MF ZERO OHM 1/10W -- 0603; AGILE_PN: 470-80866; CAD_APPROVED: Yes; FPLIST: RC0603_OV,RC0603,R603-X2,0603_CC; HEIGHT: 0.6MM; MFG_NAME01: YAGEO AMERICA; MFG_PN01: RC0603FR-070RL; ROHS: Yes; TOL: 1%; Temp Range: –55 °C to +155 °C
R246 R247 = RES: RES MF 27OHM 1/16W 5% 0402; AGILE_PN: 470-75611; CAD_APPROVED: Yes; HEIGHT: 0.45 MM; MFG_NAME01: SMEC; MFG_PN01: RC73L2Z270JTF; ROHS: Yes; Tolerance: 5%; VOLTAGE: 1/16W
TP1 = TESTLOOP: TEST POINT RED 40 MIL DRILL 180 MIL TH 109L; AGILE_PN: 210-75684; CAD_APPROVED: Yes; HEIGHT: 4.8 MM; MFG_NAME01: KEYSTONE ELECTRONICS; MFG_PN01: 5000; ROHS: Yes; SILK: LDO_5V; Temp Range: -50°C to +146°C
TP2 = TESTLOOP: TEST POINT RED 40 MIL DRILL 180 MIL TH 109L; AGILE_PN: 210-75684; CAD_APPROVED: Yes; HEIGHT: 4.8 MM; MFG_NAME01: KEYSTONE ELECTRONICS; MFG_PN01: 5000; ROHS: Yes; SILK: USB_5V; Temp Range: -50°C to +146°C
TP3 = TESTLOOP: TEST POINT RED 40 MIL DRILL 180 MIL TH 109L; AGILE_PN: 210-75684; CAD_APPROVED: Yes; HEIGHT: 4.8 MM; MFG_NAME01: KEYSTONE ELECTRONICS; MFG_PN01: 5000; ROHS: Yes; SILK: JACK; Temp Range: -50°C to +146°C
TP4 TP5 = TESTLOOP: TEST POINT BLACK 40 MIL DRILL 180 MIL TH 109L; 3D_Mechanical_Footprint_File: http://fcl.am.freescale.net/ALLEGRO/step/test_loop.STEP; AGILE_PN: 210-75683; CAD_APPROVED: Yes; HEIGHT: 4.8mm; MFG_NAME01: KEYSTONE ELECTRONICS; MFG_PN01: 5001; ROHS: Yes; SILK: GND
TP11-TP18 TP26-TP28 = TESTLOOP: TEST POINT PAD 30MIL DIA SMT, NO PART TO ORDER; 3D_Mechanical_Footprint_File: http://fcl.am.freescale.net/ALLEGRO/step/tpad_030.STEP; AGILE_PN: 211-76642; CAD_APPROVED: Yes; HEIGHT: 0.1MM; MFG_NAME01: NOTACOMPONENT; MFG_PN01: NOTACOMPONENT; ROHS: Yes
U1 = ADP197_6P: IC POWER SWITCH 40MOHM 2.3-13.2V 6WLCSP; 3D_Mechanical_Footprint_File: http://fcl.am.freescale.net/ALLEGRO/step/wlcsp6_0p5_0p98x1p48.STEP; AGILE_PN: 315-81232; CAD_APPROVED: Yes; HEIGHT: 0.675MM; MFG_NAME01: ANALOG DEVICES; MFG_PN01: ADP1290ACBZ-R7; ROHS: Yes; Temp Range: -40C to +105C; VOLTAGE: 2.3-13.2V
U2 = PESD1USB30: DIODE ESD USB 5V WLCSP5; 3D_Mechanical_Footprint_File: http://fcl.am.freescale.net/ALLEGRO/step/wlcsp5_0p4_0p82x1p22.STEP; AGILE_PN: 315-81117; CAD_APPROVED: Yes; HEIGHT: 0.6MM; MFG_NAME01: NEXPERIA; MFG_PN01: PESD1USB3S; ROHS: Yes; VOLTAGE: 5V
U20 = REG1117FIX: IC VREG LDO 5V 1.5A TO-263; 3D_Mechanical_Footprint_File: http://fcl.am.freescale.net/ALLEGRO/step/to-263-3.STEP; AGILE_PN: 315-83854; CAD_APPROVED: Yes; HEIGHT: 4.83MM; MFG_NAME01: Texas Instruments; Package Size: TO-263-4, D2Pak (3 Leads + Tab), TO-263AA; ROHS: Yes; Temp Range: 0°C ~ 125°C
U21 = LT1529_DD: IC VREG LDO 3.3V 3A 15V D2PAK5; AGILE_PN: 315-75202; CAD_APPROVED: Yes; HEIGHT: 4.572MM; MFG_NAME01: ANALOG DEVICES; ROHS: Yes
U23 = DIODEZ_SOT23: DIODE ZENER 5.6V 250MW AEC-Q101 SOT23; AGILE_PN: 480-79638; CAD_APPROVED: Yes; HEIGHT: 1.1MM; MFG_NAME01: NEXPERIA; MFG_PN01: BZX84-A5V6,215
C31 C42 = CAP_NP: CAP CER 22pF 250V 1% C0G 0805; 3D_Mechanical_Footprint_File: http://fcl.am.freescale.net/ALLEGRO/step/cc0805_ov.STEP; AGILE_PN: 150-81372; CAD_APPROVED: Yes; HEIGHT: 1.30 MM; MFG_NAME01: American Technical Ceramics; MFG_PN01: 600F220FT250XT; Package Size: 0805 (2012 Metric); Package Type: Surface Mount, MLCC; ROHS: Yes; Rated Voltage: 250V; Temp Range: -55C to +125C; Tolerance: 1%
C32 C41 = CAP_NP: CAP CER 39pF 250V 1% C0G 0805; AGILE_PN: 150-79281; CAD_APPROVED: Yes; HEIGHT: 1.44MM; MFG_NAME01: AMERICAN TECHNICAL CERAMICS CORP; MFG_PN01: 600F390FT250XT; Package Size: 0805; ROHS: Yes; Rated Voltage: 250V; Temp Range: -55C to +125C; Tolerance: 1%; VOLTAGE: 250V
C33 C37 = CAP_NP: CAP CER 180pF 50V 1% C0G 0402; AGILE_PN: 150-80736; CAD_APPROVED: Yes; FPLIST: CC0402_25,CC0402_HD,0402_CC; HEIGHT: 0.56 MM; MFG_NAME01: AVX; MFG_PN01: 04025A181FAT2A; Package Size: 0402; ROHS: Yes; Rated Voltage: 50V; Temp Range: -55C to +125C; Temp_Range: -55C to +125C; Tolerance: 1%
C34 C38 = CAP_NP: CAP CER 68pF 250V 1% C0G 0805; AGILE_PN: 150-79296; ASSY_OPT: DNP; CAD_APPROVED: Yes; FPLIST: CC0805_OV,CC0805,0805_CC; HEIGHT: 1.44MM; MFG_NAME01: AMERICAN TECHNICAL CERAMICS CORP; MFG_PN01: 600F680FT250XT; Package Size: 0805; Package Type: Tape & reel; ROHS: Yes; Rated Voltage: 250V; Temp Range: -55C to +125C; Tolerance: 1%; VOLTAGE: 250V
C35 C39 = CAP_NP: CAP CER 100pF 250V 1% C0G 0805; AGILE_PN: 150-79292; CAD_APPROVED: Yes; FPLIST: CC0805_OV,CC0805,0805_CC; HEIGHT: 1.44MM; MFG_NAME01: AMERICAN TECHNICAL CERAMICS CORP; MFG_PN01: 600F101FT250XT; Package Size: 0805; ROHS: Yes; Rated Voltage: 250V; Temp Range: -55C to +125C; Tolerance: 1%; VOLTAGE: 250V
C36 C40 = CAP_NP: CAP CER 68pF 250V 1% C0G 0805; AGILE_PN: 150-79296; CAD_APPROVED: Yes; FPLIST: CC0805_OV,CC0805,0805_CC; HEIGHT: 1.44MM; MFG_NAME01: AMERICAN TECHNICAL CERAMICS CORP; MFG_PN01: 600F680FT250XT; Package Size: 0805; Package Type: Tape & reel; ROHS: Yes; Rated Voltage: 250V; Temp Range: -55C to +125C; Tolerance: 1%; VOLTAGE: 250V
J12 = CONN_HDR_1X1_TH: HDR 1X1 TH -- 338H AU 100L; 3D_Mechanical_Footprint_File: http://fcl.am.freescale.net/ALLEGRO/step/hdr_1x1.STEP; AGILE_PN: 210-79790; ASSY_OPT: DNP; CAD_APPROVED: Yes; HEIGHT: 8.89MM; MFG_NAME01: SAMTEC; MFG_PN01: TSW-101-07-L-S; ROHS: Yes; Temp Range: -55°C to +125°C
J13 J14 = CONN_HDR_7X1: CON 1X7 SKT TH 100MIL SP 340H AU 104L; 3D_Mechanical_Footprint_File: http://fcl.am.freescale.net/ALLEGRO/step/con_1x7_skt_2p54_th.STEP; AGILE_PN: 210-81383; ASSY_OPT: DNP; CAD_APPROVED: Yes; HEIGHT: 8.636MM; MFG_NAME01: SAMTEC; MFG_PN01: SSW-107-01-G-S; ROHS: Yes; Temp Range: -55C to +125C; Temp_Range: -55C to +125C
J15 J16 = CONN_HDR_4X1: CON 1X4 SKT TH 100MIL SP 340H AU 104L; 3D_Mechanical_Footprint_File: http://fcl.am.freescale.net/ALLEGRO/step/con_skt1x4_th.STEP; AGILE_PN: 210-80462; ASSY_OPT: DNP; CAD_APPROVED: Yes; HEIGHT: 8.64MM; MFG_NAME01: SAMTEC; MFG_PN01: SSW-104-01-G-S; ROHS: Yes; Temp Range: -55°C to +125°C
R20 R27 = RES: RES MF ZERO OHM 1/8W -- 0805; AGILE_PN: 470-75442; ASSY_OPT: DNP; CAD_APPROVED: Yes; FPLIST: RC0805_OV,RC0805,RC0805_OV_3P,0805_CC; HEIGHT: 0.7 MM; MFG_NAME01: YAGEO AMERICA; MFG_PN01: RC0805JR-070RL; ROHS: Yes; Temp Range: –55 °C to +155 °C; Tolerance: 5%
R21 R26 = RES: RES MF 1.5K 1/8W 1% 0805; AGILE_PN: 470-75955; CAD_APPROVED: Yes; FPLIST: RC0805_OV,RC0805,0805_CC; HEIGHT: 0.70 MM; MFG_NAME01: BOURNS; MFG_PN01: CR0805-FX-1501ELF; ROHS: Yes; Temp Range: –55 °C to +155 °C; Tolerance: 1%
R22-R25 = RES: RES MF 2.2 OHM 1/3W 1% 0805; AGILE_PN: 470-82358; CAD_APPROVED: Yes; FPLIST: RC0805_OV,RC0805,0805_CC; HEIGHT: 0.5MM; MFG_NAME01: SUSUMU CO. LTD.; MFG_PN01: RL1220S-2R2-F; ROHS: Yes; Temp Range: -55°C to +125°C; Tolerance: 1%
R41 R133 R238 = RES: RES MF ZERO OHM 1/10W -- 0603; AGILE_PN: 470-80866; ASSY_OPT: DNP; CAD_APPROVED: Yes; FPLIST: RC0603_OV,RC0603,R603-X2,0603_CC,IND_0603HP_NSP,CC0603_OV_NSP; HEIGHT: 0.6MM; MFG_NAME01: YAGEO AMERICA; MFG_PN01: RC0603FR-070RL; ROHS: Yes; TOL: 5%; Temp Range: –55 °C to +155 °C
P1 = TP_RECT_56P_EP: NFC MODULE 4X14 23X23MM NO PART TO ORDER; AGILE_PN: 510-78458; CAD_APPROVED: Yes; HEIGHT: 2.35 MM; ROHS: Yes
C58 C61 = CAP_NP: CAP CER 10UF 10V 10% X5R 0603; AGILE_PN: 150-78675; CAD_APPROVED: Yes; FPLIST: CC0603_OV,CC0603,0603_CC_NSP; HEIGHT: 1.016MM; MFG_NAME01: MURATA; MFG_PN01: GRM188R61A106KE69D; ROHS: Yes; Rated Voltage: 10V; Temp Range: -55C to +85C; Temp_Range: -55°C to +85°C; Tolerance: 10%; VOLTAGE: 10v
C62 C63 = CAP_NP: CAP CER 22PF 50V 5% C0G 0603; AGILE_PN: 150-75189; ASSY_OPT: DNP; CAD_APPROVED: Yes; FPLIST: CC0603_OV,CC0603,0603_CC; HEIGHT: 1.016MM; MFG_NAME01: WURTH ELEKTRONIK EISOS GMBH & CO. KG (ELECTRONIC & ELECTROMEHANICAL COMP); MFG_PN01: 885012006053; Package Size: 0603; Package Type: Tape & reel; ROHS: Yes; Rated Voltage: 50V; Temp Range: -55C to +125C; Tolerance: 5%; VOLTAGE: 50V
C64 = CAP_NP: CAP CER 2.2UF 6.3V 10% X5R 0603; AGILE_PN: 150-76330; CAD_APPROVED: Yes; FPLIST: CC0603_OV,CC0603,0603_CC; HEIGHT: 0.9MM; MFG_NAME01: KEMET; MFG_PN01: C0603C225K9PAC; Package Size: 0603; Package Type: Tape&reel; ROHS: Yes; Rated Voltage: 6.3V; Temp Range: -55C to +85C; Tolerance: 10%; VOLTAGE: 6.3V
D8 = LED: LED GRN SGL 20MA 2V SMT 0603; 3D_Mechanical_Footprint_File: http://fcl.am.freescale.net/ALLEGRO/step/led_0603_h020.STEP; AGILE_PN: 370-76819; CAD_APPROVED: YES; HEIGHT: 0.5 mm; MFG_NAME01: WURTH ELEKTRONIK EISOS GMBH & CO. KG (ELECTRONIC & ELECTROMEHANICAL COMP); MFG_PN01: 150060VS55040; Package Size: 0603 (1608 metric); SILK: SDA
J28 = CONN_HDR_2X1: HDR 1X2 TH 100MIL SP 339H AU 98L; 3D_Mechanical_Footprint_File: http://fcl.am.freescale.net/ALLEGRO/step/hdr102_338h.STEP; AGILE_PN: 210-75439; ASSY_OPT: DNP; CAD_APPROVED: YES; FPLIST: HDR102,SH_HDR102_BOTTOM; HEIGHT: 8.71 MM; MFG_NAME01: SAMTEC; MFG_PN01: TSW-102-07-G-S; ROHS: Yes; Temp Range: -55°C to +125°C
J29 = CONN_HDR_5X2: HDR 2X5 TH 50MIL CTR 167H AU 91L; AGILE_PN: 210-80192; CAD_APPROVED: Yes; FPLIST: hdr_5X2_ftsh_th,hdr_5X2_ftsh_th_nsp; HEIGHT: 4.25MM; MFG_NAME01: ANYTRONIC CORPORATION LIMITED; MFG_PN01: 0922S0205011N6T-2LF; ROHS: Yes
L4 L5 = BEAD: IND FER BEAD 330OHM@100MHZ 2.5A -- SMT; 3D_Mechanical_Footprint_File: http://fcl.am.freescale.net/ALLEGRO/step/ind_0805.STEP; AGILE_PN: 180-30021; CAD_APPROVED: YES; HEIGHT: 1.05 MM; MFG_NAME01: TDK; MFG_PN01: MPZ2012S331AT000; PART_TYPE: FERRITE; ROHS: Yes; Temp Range: -55°C to +125°C; Tolerance: 25%
R97 R99 = RES: RES MF 10.0K 1/16W 1% AEC-Q200 0402; AGILE_PN: 470-75416; CAD_APPROVED: Yes; FPLIST: RC0402_25,RC0402_HD,0402_CC; HEIGHT: 0.4MM; MFG_NAME01: KOA SPEER; MFG_PN01: RK73H1ETTP1002F; ROHS: Yes; TOL: 5%; Temp Range: –55 °C to +155 °C; Tolerance: 1%
R98 R100 = RES: RES MF ZERO OHM 1/10W -- 0603; AGILE_PN: 470-80866; CAD_APPROVED: Yes; FPLIST: RC0603_OV,RC0603,R603-X2,0603_CC,IND_0603HP_NSP,CC0603_OV_NSP; HEIGHT: 0.6MM; MFG_NAME01: YAGEO AMERICA; MFG_PN01: RC0603FR-070RL; ROHS: Yes; Temp Range: –55 °C to +155 °C
R101 R102 = RES: RES MF 33.0 OHM 1/16W 1% 0402; AGILE_PN: 470-75790; CAD_APPROVED: Yes; FPLIST: RC0402_25,RC0402_HD,RC0402_X2,0402_CC; HEIGHT: 0.4MM; MFG_NAME01: VISHAY; MFG_PN01: CRCW040233R0FKEDC; ROHS: Yes; Tolerance: 1%
R103 = RES: RES MF 4.70K 1/16W 1% 0402; AGILE_PN: 470-75418; CAD_APPROVED: Yes; FPLIST: RC0402_25,RC0402_HD,0402_CC; HEIGHT: 0.4mm; MFG_NAME01: WALSIN TECHNOLOGY CORP.; MFG_PN01: WR04X4701FTL; ROHS: Yes; TOL: 1%; Tolerance: 1%; VOLTAGE: 1/16W
R104 = RES: RES MF 270 OHM 1/10W 1% AEC-Q200 0402; AGILE_PN: 470-30782; CAD_APPROVED: Yes; FPLIST: RC0402_25,RC0402_HD,0402_CC; HEIGHT: 0.40 MM; MFG_NAME01: KOA SPEER; MFG_PN01: RK73H1ETTP2700F; ROHS: Yes; Temp Range: -55°C to +155°C; Temp_Range: -55°C to +155°C; Tolerance: 1%
R105 R108 = RES: RES MF 10.0K 1/16W 1% AEC-Q200 0402; AGILE_PN: 470-75416; CAD_APPROVED: Yes; FPLIST: RC0402_25,RC0402_HD,0402_CC; HEIGHT: 0.4MM; MFG_NAME01: KOA SPEER; MFG_PN01: RK73H1ETTP1002F; ROHS: Yes; Temp Range: –55 °C to +155 °C; Tolerance: 1%
R106 = RES: RES MF 4.70K 1/16W 1% 0402; AGILE_PN: 470-75418; ASSY_OPT: DNP; CAD_APPROVED: Yes; FPLIST: RC0402_25,RC0402_HD,0402_CC; HEIGHT: 0.4mm; MFG_NAME01: WALSIN TECHNOLOGY CORP.; MFG_PN01: WR04X4701FTL; ROHS: Yes; TOL: 1%; Tolerance: 1%; VOLTAGE: 1/16W
R107 = RES: RES MF 10.0K 1/16W 1% AEC-Q200 0402; AGILE_PN: 470-75416; ASSY_OPT: DNP; CAD_APPROVED: Yes; FPLIST: RC0402_25,RC0402_HD,0402_CC; HEIGHT: 0.4MM; MFG_NAME01: KOA SPEER; MFG_PN01: RK73H1ETTP1002F; ROHS: Yes; Temp Range: –55 °C to +155 °C; Tolerance: 1%
U26 = PK20DX128V_QFN_32P: IC MCU FLASH 128KB 50MHZ 1.71-3.6V QFN32; AGILE_PN: 344-01231; CAD_APPROVED: Yes; HEIGHT: 1MM; MFG_NAME01: FREESCALE SEMICONDUCTOR; ROHS: Yes; VOLTAGE: 1.71-3.6V
U27 = NL27WZ14_6P: IC INV DUAL SCHMITT TRIGGER 1.65-5.5V UDFN6; 3D_Mechanical_Footprint_File: http://fcl.am.freescale.net/ALLEGRO/step/udfn6_1p45x1_0p5mm.STEP; AGILE_PN: 315-82857; CAD_APPROVED: Yes; HEIGHT: 0.55 MM; MFG_NAME01: ON SEMICONDUCTOR; ROHS: Yes; Temp Range: -55°C to +125°C; VOLTAGE: 1.65-5.5V
U28 = RCLAMP1654P_NEW: DIODE TVS ARRAY 3 5.5V SLP1616P6; 3D_Mechanical_Footprint_File: http://fcl.am.freescale.net/ALLEGRO/step/slp1616p6.step; AGILE_PN: 480-78843; CAD_APPROVED: Yes; HEIGHT: 0.65MM; MFG_NAME01: SEMTECH CORP; ROHS: Yes; Rated Voltage: 5.5V; VOLTAGE: 5.5V
X1 = XTAL_CS: XTAL 8.00MHZ RSN CERAMIC -- SMT; 3D_Mechanical_Footprint_File: http://fcl.am.freescale.net/ALLEGRO/step/xtal3_3p35x1p45_sm.STEP; AGILE_PN: 230-78262; CAD_APPROVED: Yes; HEIGHT: 0.8 MM; MFG_NAME01: MURATA; MFG_PN01: CSTNE8M00G550000R0; ROHS: Yes; Temp Range: -40 to +85°C; Temp_Range: -40 to +85°C

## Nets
GND: C1.2 C2.2 C3.2 C4.2 C5.2 C6.2 C7.2 C8.2 C9.2 C10.2 C11.2 C12.2 C13.2 C14.2 C15.2 C16.2 C17.2 C18.2 C19.2 C20.2 C21.2 C22.2 C23.2 C24.2 C25.2 C26.2 C27.2 C28.2 C29.2 C30.2 C33.2 C34.2 C35.2 C36.2 C37.2 C38.1 C39.1 C40.1 C43.2 C52.2 C54.2 C57.2 C58.2 C59.2 C60.2 C61.2 C62.2 C63.2 C64.2 C65.2 D1.A D11.C(CATHODE) D12.C(CATHODE) D13.C(CATHODE) D14.1(ANODE) J5.A1(GND1) J5.A12(GND2) J5.B1(GND3) J5.B12(GND4) J10.1 J10.2 J11.1 J11.2 J13.4 J14.4 J27.A1(GND1) J27.A12(GND2) J27.B1(GND3) J27.B12(GND4) J29.3(A2) J29.5(A3) L2.2 L3.3 L5.1 P1.5 P1.7 P1.9 P1.45 P1.48 P1.50 P1.57(EPAD) R10.2 R11.2 R19.2 R28.2 R105.2 R107.2 R126.2 R127.2 R163.2 R164.2 TP4.1(Pin1) TP5.1(Pin1) U1.C2(GND) U2.B1(GND) U20.1(GND) U21.3(GND) U21.6(TAB) U23.1(ANODE) U26.2(VSS1) U26.8(VSSA) U26.33(EPAD) U27.2(GND) U28.7(GND) X1.2 ; also on sheet 6 7 8 9 10
P3V3_BRD: J42.2 ; also on sheet 6 7 8 9 10
P3V3_LDO: C22.1 C23.1 C24.1 C25.1 C26.1 C27.1 J1.1 J2.1 J4.1 J7.1 J34.1 J42.1 J43.1 R9.1 U21.1(VOUT) U21.2(SENSE)
P3V3_SDA: C57.1 C58.1 C59.1 C60.1 C65.1 J29.1(A1) R97.1 R99.2 R104.1 R108.1 U26.1(VDD1) U26.7(VDDA) U26.11(VBAT) U27.5(VCC) ; also on sheet 6
P3V3A_BRD: C28.1 R12.2 ; also on sheet 10
P5V0_SDA_USB_CONN_VBUS: J27.A4(VBUS1) J27.A9(VBUS2) J27.B4(VBUS3) J27.B9(VBUS4) L4.1 U28.6(VBUS)
P5V_BRD: J1.3 J2.3 J3.2 J4.3 J7.3 R194.1 U21.5(VIN) ; also on sheet 7
P5V_JACK: J3.4 J8.3 U23.3(CATHODE)
P5V_LDO: C2.1 C3.1 C4.1 C5.1 J3.1 R2.1 TP1.1(Pin1) U20.2(VOUT) U20.4(VOUT)
P5V_SDA: C61.1 L4.2 R103.1 R106.1 U26.6(VREGIN)
P5V_USB: C14.1 C15.1 C16.1 C17.1 C52.1 J3.3 L1.1 R13.1 TP2.1(Pin1) U1.A1(VIN) U1.B1(VIN1)
P7V_JACK: D14.3(CATHODE) D15.A J8.1 ; also on sheet 7
VBAT: C18.1 C19.1 C20.1 J4.2 P1.49
VBATPWR: C12.1 C13.1 P1.46 R3.2
VBUS: D1.C J5.A4(VBUS1) J5.A9(VBUS2) J5.B4(VBUS3) J5.B9(VBUS4) L1.2
VDDIO: J34.2 P1.44
VDDPA: J7.2 P1.52
VIN+: D10.3(AC1) J9.1(Pin) R6.1
VIN-: D10.4(AC2) J9.2 J9.3 R8.1
AD_VTUNE1: R238.2 ; also on sheet 7
AD_VTUNE2: R41.2 ; also on sheet 7
ANT_1: J15.2 J15.3 J16.2 J16.3 R22.2 R23.2 R24.2 R25.2
AUX3: R133.2 ; also on sheet 10
C_TX1: C39.2 C40.2 C41.2 C42.2 R24.1 R25.1 R27.2
C_TX2: C31.2 C32.2 C35.1 C36.1 R20.2 R22.1 R23.1
RXN: J13.6 J14.6 P1.4 R26.2 R27.1
RXP: J13.2 J14.2 P1.10 R20.1 R21.1
SDA_EXTAL: C63.1 U26.17(EXTAL0/PTA18/FTM0_FLT2/FTM_CLKIN0) X1.3
SDA_JTAG_TCLK: J29.4(B2) U26.12(JTAG_TCLK/SWD_CLK/EZP_CLK/TSI0_CH1/PTA0/~{UART0_CTS}/~{UART0_COL}/FTM0_CH5)
SDA_JTAG_TDI: J29.8(B4) U26.13(JTAG_TDI/EZP_DI/TSI0_CH2/PTA1/UART0_RX/FTM0_CH6)
SDA_JTAG_TDO: J29.6(B3) U26.14(JTAG_TDO/TRACE_SWO/EZP_DO/TSI0_CH3/PTA2/UART0_TX/FTM0_CH7)
SDA_JTAG_TMS: J29.2(B1) R108.2 U26.15(JTAG_TMS/SWD_DIO/TSI0_CH4/PTA3/~{UART0_RTS}/FTM0_CH0)
SDA_LED: D8.C(CATHODE) TP17.1(Pin1) U26.29(PTD4/SPI0_PCS1/~{UART0_RTS}/FTM0_CH4/EWM_IN/LLWU_P14)
SDA_LED_R: D8.A(ANODE) R104.2
SDA_RST: J29.10(B5) R103.2 R105.1 TP16.1(Pin1) U26.19(~{RESET})
SDA_RST_TGTMCU_B: J28.2 U26.21(ADC0_SE9/TSI0_CH6/PTB1/I2C0_SDA/FTM1_CH1/FTM1_QD_PHB)
SDA_RST_TGTMCU_J_B: J28.1 ; also on sheet 6
SDA_SPI0_CS: R110.2 TP15.1(Pin1) U26.23(ADC0_SE4B/CMP1_IN0/TSI0_CH15/PTC2/SPI0_PCS2/~{UART1_CTS}/FTM0_CH1/I2S0_TX_FS)
SDA_SPI0_RST_B: R109.2 TP14.1(Pin1) U26.22(ADC0_SE15/TSI0_CH14/PTC1/SPI0_PCS3/~{UART1_RTS}/FTM0_CH0/I2S0_TXD0/LLWU_P6)
SDA_SPI0_SCK: U26.26(PTC5/SPI0_SCK/LPTMR0_ALT2/I2S0_RXD0/CMP0_OUT/LLWU_P9) ; also on sheet 6
SDA_SPI0_SIN: U26.28(CMP0_IN1/PTC7/SPI0_SIN/USB_SOF_OUT/I2S0_RX_FS) ; also on sheet 6
SDA_SPI0_SOUT: U26.27(CMP0_IN0/PTC6/SPI0_SOUT/PDB0_EXTRG/I2S0_RX_BCLK/I2S0_MCLK/LLWU_P10) ; also on sheet 6
SDA_SWD_EN: R109.1 U27.6(Y1) ; also on sheet 6
SDA_SWD_EN_B: R98.2 U26.16(~{NMI}/~{EZP_CS}/TSI0_CH5/PTA4/FTM0_CH1/LLWU_P3)
SDA_SWD_EN_B_R: R97.2 R98.1 U27.1(A1)
SDA_SWD_OE: R110.1 U27.4(Y2) ; also on sheet 6
SDA_SWD_OE_B: R100.2 U26.20(ADC0_SE8/TSI0_CH0/PTB0/I2C0_SCL/FTM1_CH0/FTM1_QD_PHA/LLWU_P5)
SDA_SWD_OE_B_R: R99.1 R100.1 U27.3(A2)
SDA_USB_CC1: J27.A5(CC1) R164.1 TP11.1(Pin1)
SDA_USB_CC2: J27.B5(CC2) R163.1 TP26.1(Pin1)
SDA_USB_CONN_DN: J27.A7(D-_1) J27.B7(D-_2) R101.1 U28.1(DM)
SDA_USB_CONN_DP: J27.A6(D+_1) J27.B6(D+_2) R102.1 U28.2(DP)
SDA_USB_DN: R101.2 U26.4(USB0_DM)
SDA_USB_DP: R102.2 U26.3(USB0_DP)
SDA_USB_P5V_SENSE: R106.2 R107.1 TP18.1(Pin1) U26.30(ADC0_SE6B/PTD5/SPI0_PCS2/~{UART0_CTS}/~{UART0_COL}/FTM0_CH5/~{EWM_OUT})
SDA_USBSHIELD: J27.SH1 J27.SH2 J27.SH3 J27.SH4 L5.2
SDA_VOUT33: C64.1 U26.5(VOUT33) ; also on sheet 6
SDA_XTAL: C62.1 U26.18(XTAL0/PTA19/FTM1_FLT0/FTM_CLKIN1/LPTMR0_ALT1) X1.1
SEL_USBP: U1.C1(EN) ; also on sheet 10
TC_EXTAL_TP: TP12.1(Pin1) U26.10(EXTAL32)
TC_XTAL_TP: TP13.1(Pin1) U26.9(XTAL32)
TX1: C37.1 C38.2 C41.1 C42.1 J13.5 J14.5 P1.6 R26.1
TX2: C31.1 C32.1 C33.1 C34.1 J13.3 J14.3 P1.8 R21.2
UART1_RX_TGTMCU_R: U26.25(PTC4/SPI0_PCS0/UART1_TX/FTM0_CH3/CMP1_OUT/LLWU_P8) ; also on sheet 6
UART1_TX_TGTMCU_R: U26.24(CMP1_IN1/PTC3/SPI0_PCS1/UART1_RX/FTM0_CH2/I2S0_TX_BCLK/LLWU_P7) ; also on sheet 6
USB0_RDN: R243.1 ; also on sheet 9
USB0_RDP: R242.1 ; also on sheet 9
USB_CC1: J5.A5(CC1) R11.1 TP27.1(Pin1)
USB_CC2: J5.B5(CC2) R10.1 TP28.1(Pin1)
USB_DN: J5.A7(D-_1) J5.B7(D-_2) U2.A2(CH1_IN-)
USB_DP: J5.A6(D+_1) J5.B6(D+_2) U2.A1(CH1_IN+)
USB_SHLD: J5.SH1 J5.SH2 J5.SH3 J5.SH4 L2.1
USB_VBUS: C21.1 P1.47 R4.2
USB_VBUS_IN: C54.1 R4.1 U1.A2(VOUT) U1.B2(VOUT1) ; also on sheet 9
VTUNE1: C30.1 J13.1 P1.11 R19.1 R238.1
VTUNE2: C43.1 J13.7 R28.1 R132.2
VUP: C8.1 C9.1 J12.1 P1.51 R1.2
N26142081: J15.1 J16.1
N26142083: J15.4 J16.4
N26219711: C10.1 C11.1 J2.2 R3.1
N26219920: C6.1 C7.1 J1.2 R1.1
N27584814: J43.2 R12.1
N27604002: C1.1 D15.C U20.3(VIN)
N27718348: P1.3 R41.1 R132.1 R133.1
N27772657: L3.2 R14.1
N27772661: C29.1 J8.2 R14.2
N27773045: D10.1(+DC) L3.1 R6.2 TP3.1(Pin1)
N27773055: D10.2(-DC) L3.4 R8.2
N27843592: D11.A(ANODE) R9.2
N27844096: D12.A(ANODE) R2.2
N27844130: D13.A(ANODE) R13.2
N27880470: R126.1 R243.2 R247.2
N27880481: R127.1 R242.2 R246.2
N28140140: R194.2 U21.4(~{SHDN})
N28780711: R247.1 U2.C2(CH1_OUT-)
N28780714: R246.1 U2.C1(CH1_OUT+)

Not connected (* = marked no-connect by the designer): D14 2(NC)*; J5 A2(TX1+)* A3(TX1-)* A8(SBU1)* A10(RX2-)* A11(RX2+)* B2(TX2+)* B3(TX2-)* B8(SBU2)* B10(RX1-)* B11(RX1+)*; J14 1* 7*; J27 A2(TX1+)* A3(TX1-)* A8(SBU1)* A10(RX2-)* A11(RX2+)* B2(TX2+)* B3(TX2-)* B8(SBU2)* B10(RX1-)* B11(RX1+)*; J29 7(A4)* 9(A5)*; U23 2(NC)*; U26 31(ADC0_SE7B/PTD6/SPI0_PCS3/UART0_RX/FTM0_CH6/FTM0_FLT0/LLWU_P15)* 32(PTD7/CMT_IRO/UART0_TX/FTM0_CH7/FTM0_FLT1)*; U28 3(USB_ID)* 4(NC1)* 5(NC2)*

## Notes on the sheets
sheet 1
- Table of Contents
- Revisions
- 1
- TITLE PAGE, NOTES
- Rev
- Description
- Date
- Approved
- 2
- Block Diagram
- A
- Release
- 9 FEB 2022
- Michael Neurohr
- 3
- POWER
- Set J1, J2, J3, J4 default close with 2-3
  Set J43 default open
  Change U14 to NTS0104GU12
  Add R250, R251, R252
  Change R136, R137, R213 to 3-pin resistor
  Remove jumpers on J59
  Add U38
  Add C88~C109
  Change U20 to LM1086CS-5.0/NOPB
  Add R6 (DNP) and R8 (DNP)
  Change U1 to ADP1290ACBZ -R7
  Change D1 to PTVS5V0P1UTP,115
  Place C26, C27 before J34
  Release
- 4
- RF
- 5
- SPI/I2C/ATX/CT
- 6
- GPIO/DEBUG
- B
- 14 OCT 2022
- Michael Neurohr
- 7
- ANALOG/CONTROL
- 8
- OPENSDA
- 9
- LEVEL SHIFT
- 10
- AUDUINO
- Change R55, R82, R83 to 2.2K
  Release (Schematic Change Only)
- B1
- 28 NOV 2022
- Michael Neurohr
- PNEV7642A
- REF DES
- JUMPER(DEFAULT)
- PAGE NAME
- J8,J34,J42
- 1-2
- 03 POWER
- J1,J2,J3,J4
- 2-3
- 03 POWER
- J7,J43
- NONE
- 03 POWER
- J55,J56,J57,J58,J68
- 1-2, 3-4, 5-6, 7-8
- 05 SPI/I2C/ATX/CT
- J54
- 1-3, 2-4, 5-7, 6-8
- 05 SPI/I2C/ATX/CT
- J59
- NONE
- 05 SPI/I2C/ATX/CT
- J60
- 1-2, 3-4, 5-6, 7-8, 9-10,
   11-12
- 06 GPIO/DEBUG
- J63,J64,J65
- 1-2
- 06 GPIO/DEBUG
- J17
- 2-3
- 06 GPIO/DEBUG
- J66,J67
- NONE
- 06 GPIO/DEBUG
- J19
- 1-2, 3-4, 5-6
- 07 ANALOG/CONTROL
- J20,J45,J61,J62
- 1-2
- 07 ANALOG/CONTROL
- J22
- 2-3
- 07 ANALOG/CONTROL
- J18,J24,J25,J26
- NONE
- 07 ANALOG/CONTROL
- J30,J31,J32
- 1-2
- 09 LEVEL SHIFT
- J23,J52,J53
- NONE
- 10 ARDUINO
- REF DES
- ASSY_OPT
- PAGE NAME
- C6,C7,C8,C10,C12,C14,C18,C21,
  C52,C54,R6,R8,R194
- DNP
- 03 POWER
- 1. Interrupted lines coded with the same letter or letter
      combinations are electrically connected.
- C34,C38,J12,J13,J14,J15,J16,
  R19,R20,R27,R28,R41,R133,R238
- DNP
- 04 RF
- C88,C90,C93,C95,C97,R18,R42,
  R44,R45,R87,R88,R172,R173,
  R174,R179
- DNP
- 05 SPI/I2C/ATX/CT
- 2. Device type number is for reference only. The number
      varies with the manufacturer.
- C99,C101,R69,R89,R138,R141
- DNP
- 06 GPIO/DEBUG
- 3. Special signal usage:
- C55,C56,C82,C83,C84,C85,C86,
  C103,C104,C105,R165,R239,
  R240,U22,Y1
- DNP
- 07 ANALOG/CONTROL
- _B Denotes - Active-Low Signal
- <> or [] Denotes - Vectored Signals
- C62,C63,J28,R106,R107,R109,
  R110
- DNP
- 08 OPENSDA
- 4. Interpret diagram in accordance with American
  National Standards Institute specifications, current
  revision, with the exception of logic block symbology.
- J33,J44,R115
- DNP
- 09 LEVEL SHIFT
- J41,R39,R40,R81,R95,R134,
  R135,R139,R144,R145,R146,
  R147,R151,R154,R166,R167,
  R214,R215,R216,R217,R219,
  R220,R221,R222,R223,R224,
  R225,R226,R227,R228,R231,
  R232,R233,R234,R235,R236,R241
- DNP
- 10 ARDUINO
- REF DES
- SWITCH(DEFAULT)
- PAGE NAME
- SW6
- 1-2
- 07 ANALOG/CONTROL
- SW5,SW7
- 2-3
- 07 ANALOG/CONTROL
sheet 2
- PNEV7642A: BLOCK SCHEME
- PNEV7642A: POWER TREE
sheet 3
- POWER SECTION
- i
- Layout Note: Filter (VUP/VBAT/VBATPWR)
  ===================================
  Place Filter section & Decaps as close as possible to the Module
- 5V (1A max)
- VUP
  (3.3V/5.0V)
- i
- Layout Note: LDO
  ==============
  Provide GND Copper PAD 1.5 square inch
  on Top & Bottom for thermal (centered to TAB),
  Add multiple Vias for thermal transfer
- VBATPWR
  (3.3V/5.0V)
- i
- Layout Note: Jumper SILK Text
  ==============
  1-2: LDO 5V
  3-2: USB 5V (default)
  4-2: JACK 5V
- USB TYPE C
- VBAT
  (3.3/5.0V)
- USB_VBUS
  (5.0V)
- i
- Layout Note:
  ==========
  Maintain 90 ohm differential impedance
- i
- Layout Note:
  ==========
  Place ESD and EMI filter close to USB Connector
- VDDPA
  (3.3V/5V)
- i
- Note:USB_CC monitor
  default (2.0:500mA, 3.1:900mA): <0.66V
  1.5A: >0.66V & <1.23V
  3A: >1.23V
- 3.3V (0.8A max)
- VDDIO
  (3.3V)
- PNEV7642MA INTERFACE
- i
- Note: Input supply can be either 5V/1A or higer  (like 7.5V/1A) as long as U20 is not hot.
  It could be up to 12V by removing R5 for Arduino ONLY)
  D10 has 0.3V drop at 1A (see more from datasheet).
  DNP D10 and populate R6, R8 if D10 drop impacts application.
- GND
- Input Supply: 7.5V/1A (default)
- GND
- i
- Note:low pass filter
  cut frequency: 16KHz
- GROUND POINTS
- GND
- EPAD
- Layout Note:
  Place close to Module
- Layout Note:
  Place at board edge
- i
- Layout Note: PWR Plug
  ==============
  Polarity legend on the Silk
  close to connector
sheet 4
- NFC ANTENNA INTERFACE
- ANTENNA MATCHING
- PCB ANTENNA 45 x 45 mm
- PNEV7642MA INTERFACE
- 45mm x 45mm
- 100mil pitch
- LAYOUT ANTENNA
- i
- Layout Note: (RF Critical)
  =========
  Reuse 45mm x45mm Antenna.Zip Layout received from
   BLR Team for placement, Routing. Should reproduce the Original design without Mismatch
- i
- Layout Note:
  =========
  Refer/Reuse PNEV5180B's Layout for placement, Routing
- i
- Layout Note:
  =========
  Place discrete components as close as possible to Module
sheet 5
- OpenSDA Interface
- USB TYPE C
- TYPE C
- SHORTING HEADER
  ON BOTTOM LAYER
- i
- Note:USB_CC monitor
  default (2.0:500mA, 3.1:900mA): <0.66V
  1.5A: >0.66V & <1.23V
  3A: >1.23V
- PU/PD LOGIC:
  SERIAL INTERFACE
  IS ALWAYS RESET
  WHEN USB PORT
  IS DISCONNECTED
- HW Designer: Rafael del Rey
- OpenSDA INTERFACE JTAG CONNECTOR
- {For enablement purposes only}
